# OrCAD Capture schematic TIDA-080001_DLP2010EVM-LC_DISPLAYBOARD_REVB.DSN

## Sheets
1 P05: DLPA2005: size D
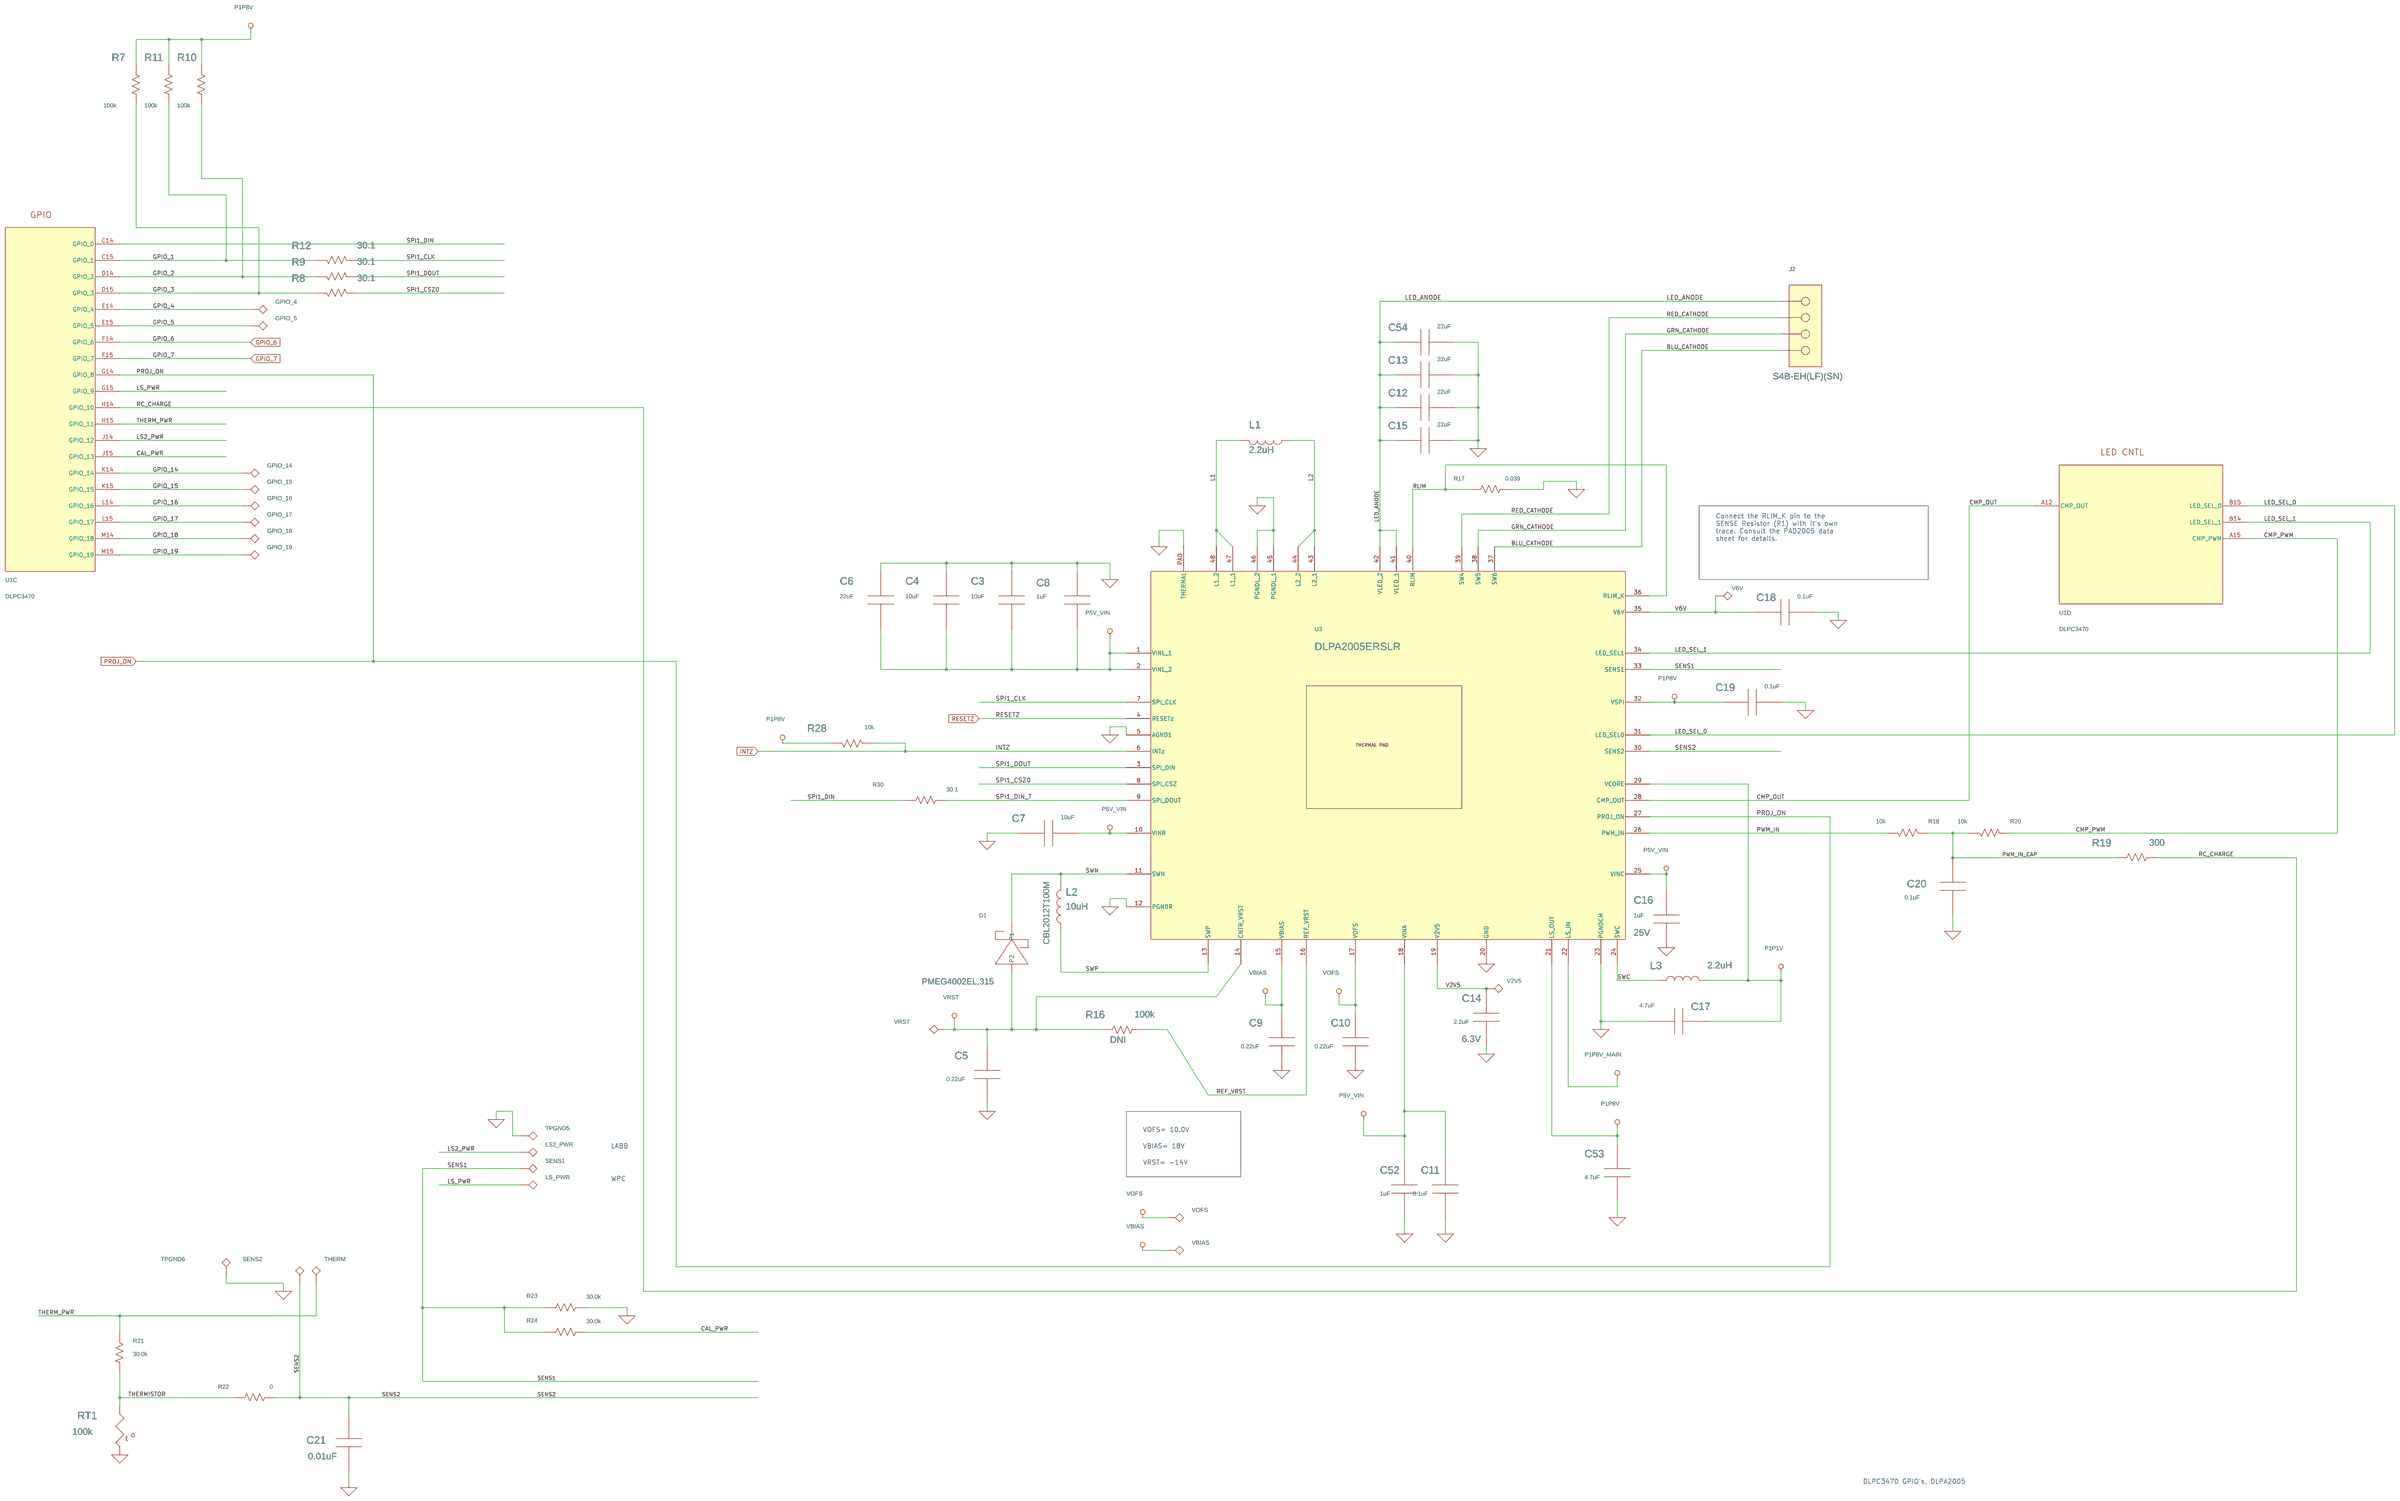
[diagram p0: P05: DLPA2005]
2 P07: Notice
3 P04: DMD Connection: size D
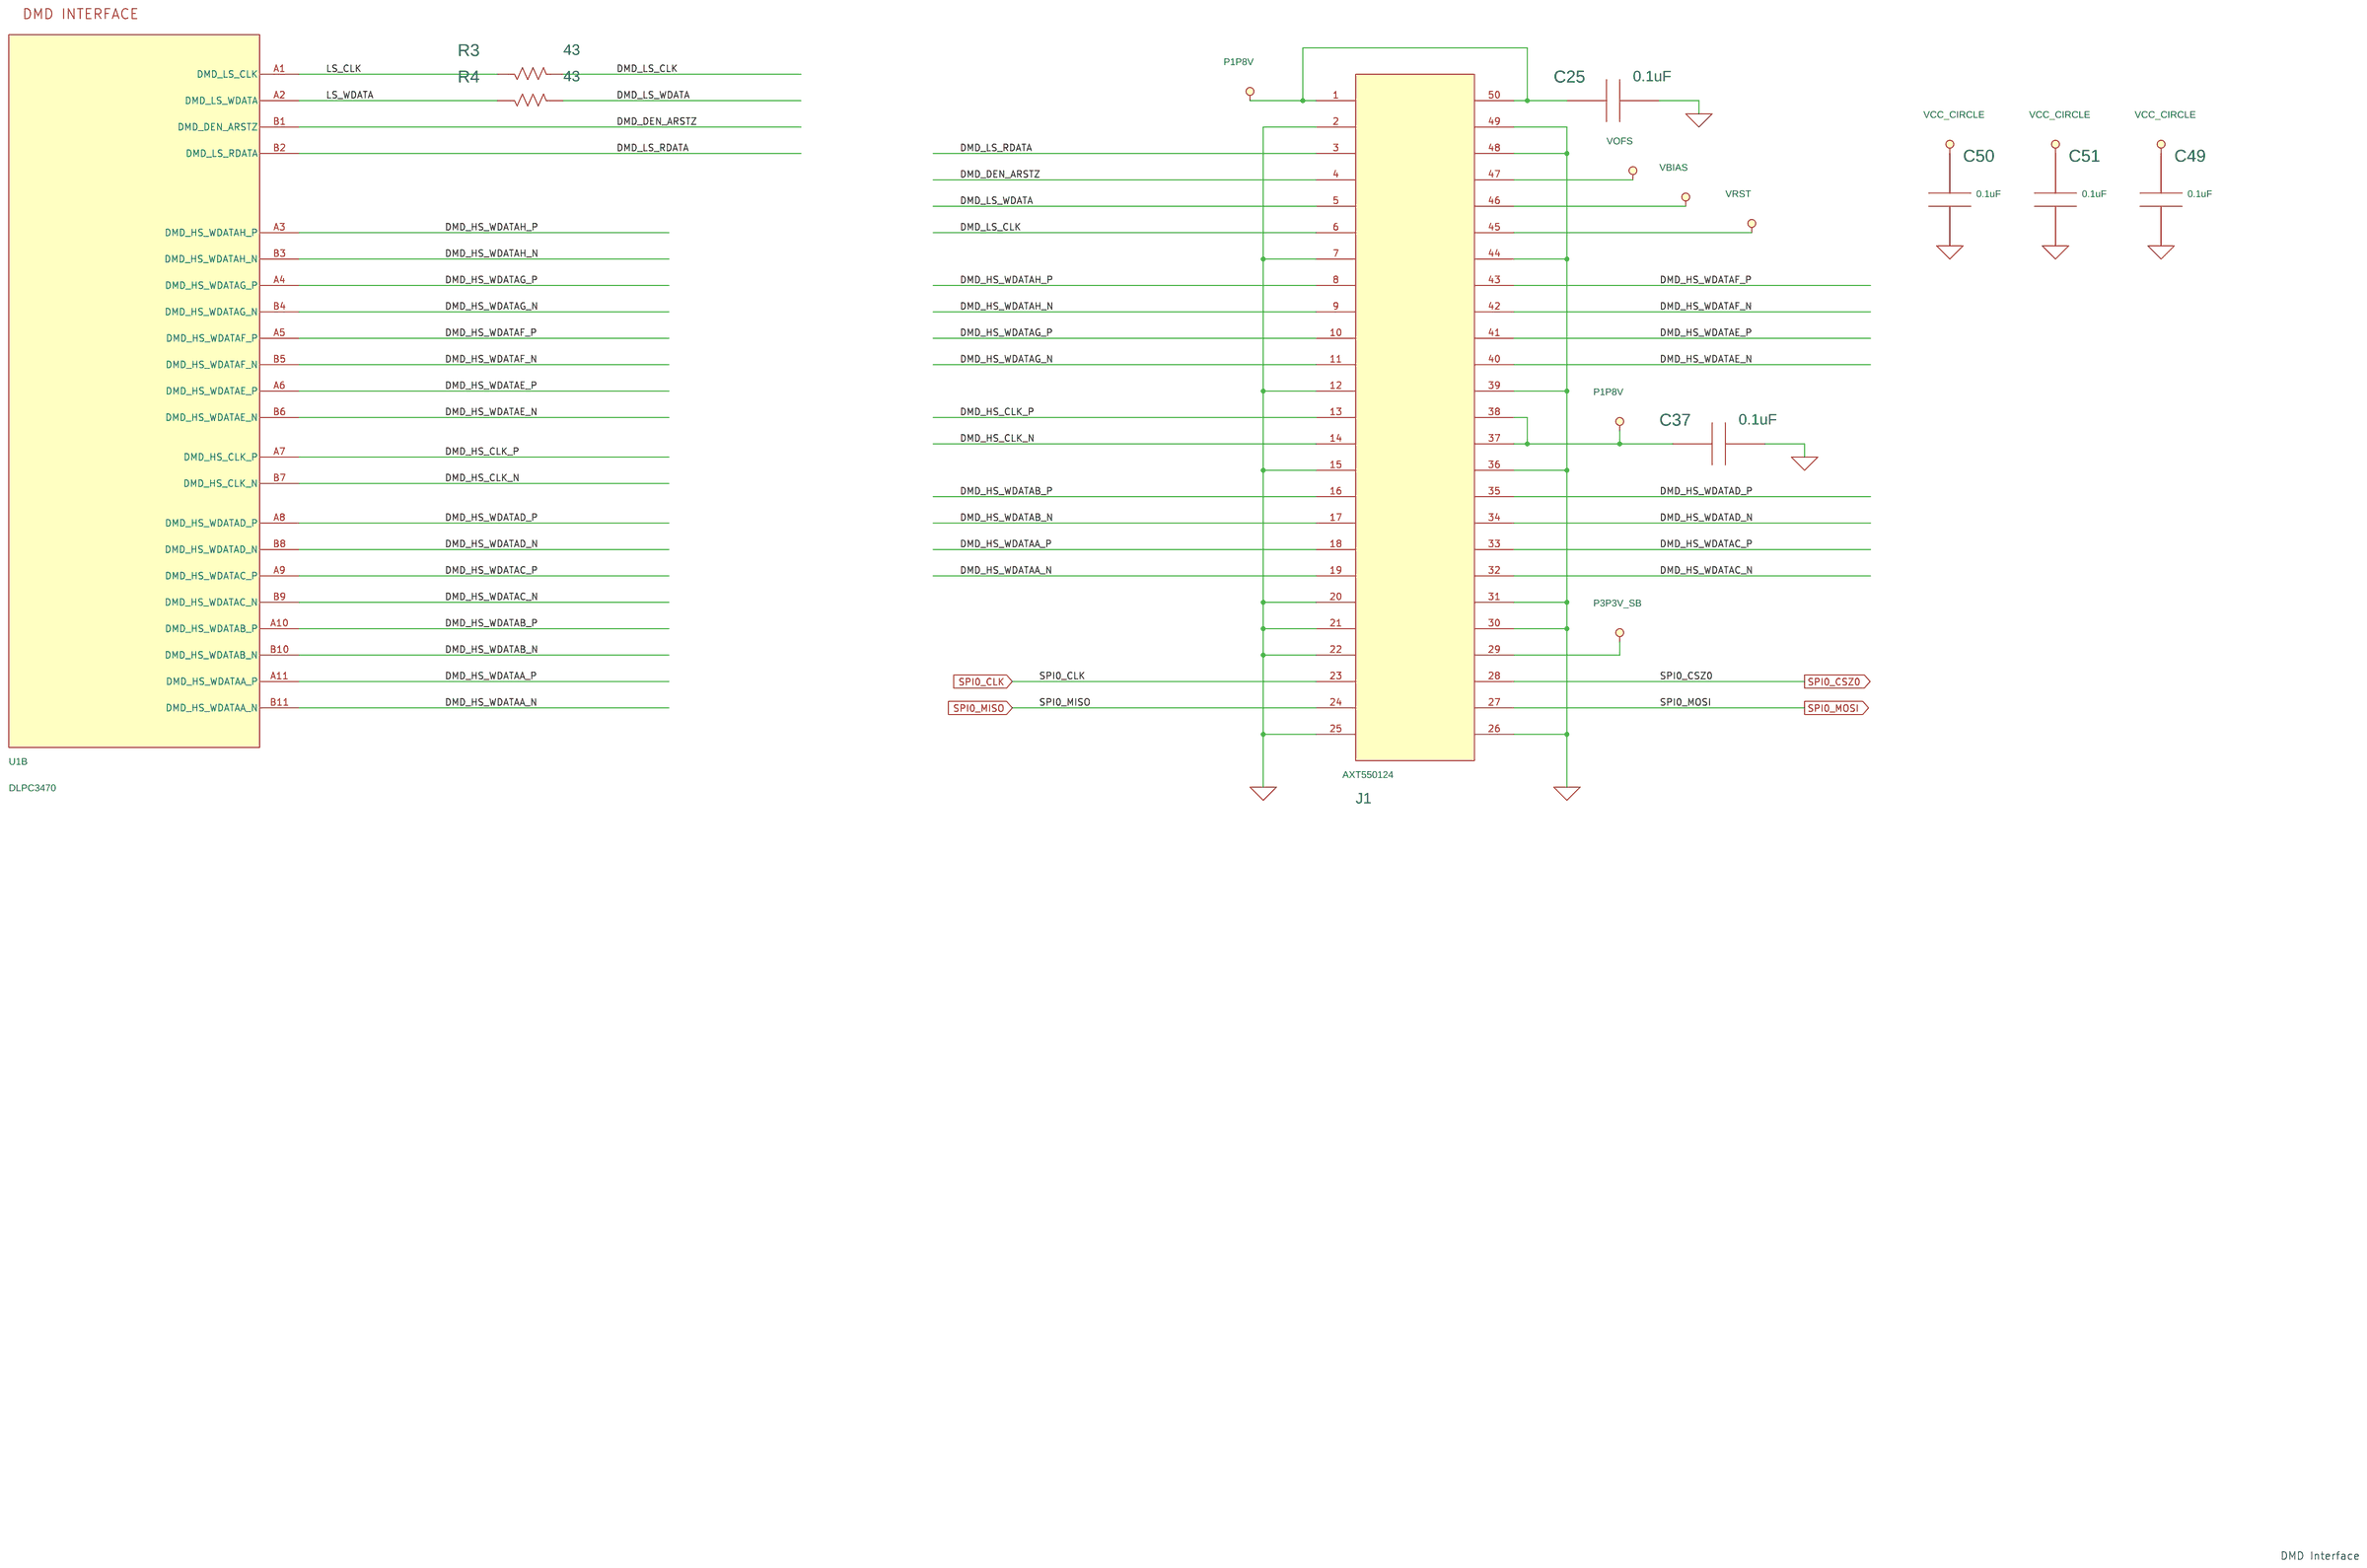
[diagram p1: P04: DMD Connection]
4 P01: DLP2010EVM-LC: title: TIDA-080001_DLP® 2010 Light Control Display Board; rev: B; company: Texas Instruments Inc.
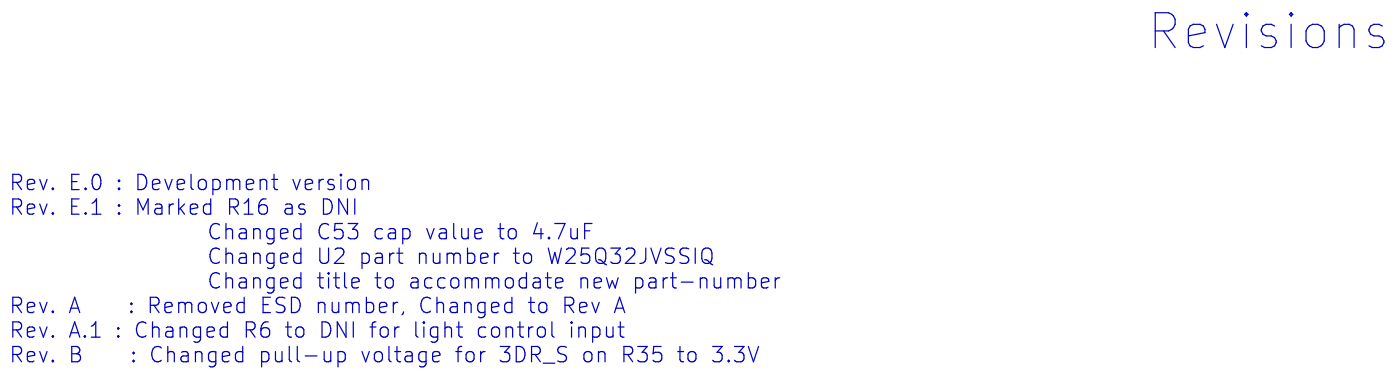
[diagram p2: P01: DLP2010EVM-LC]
5 P02: DLPC3470, Flash: size D
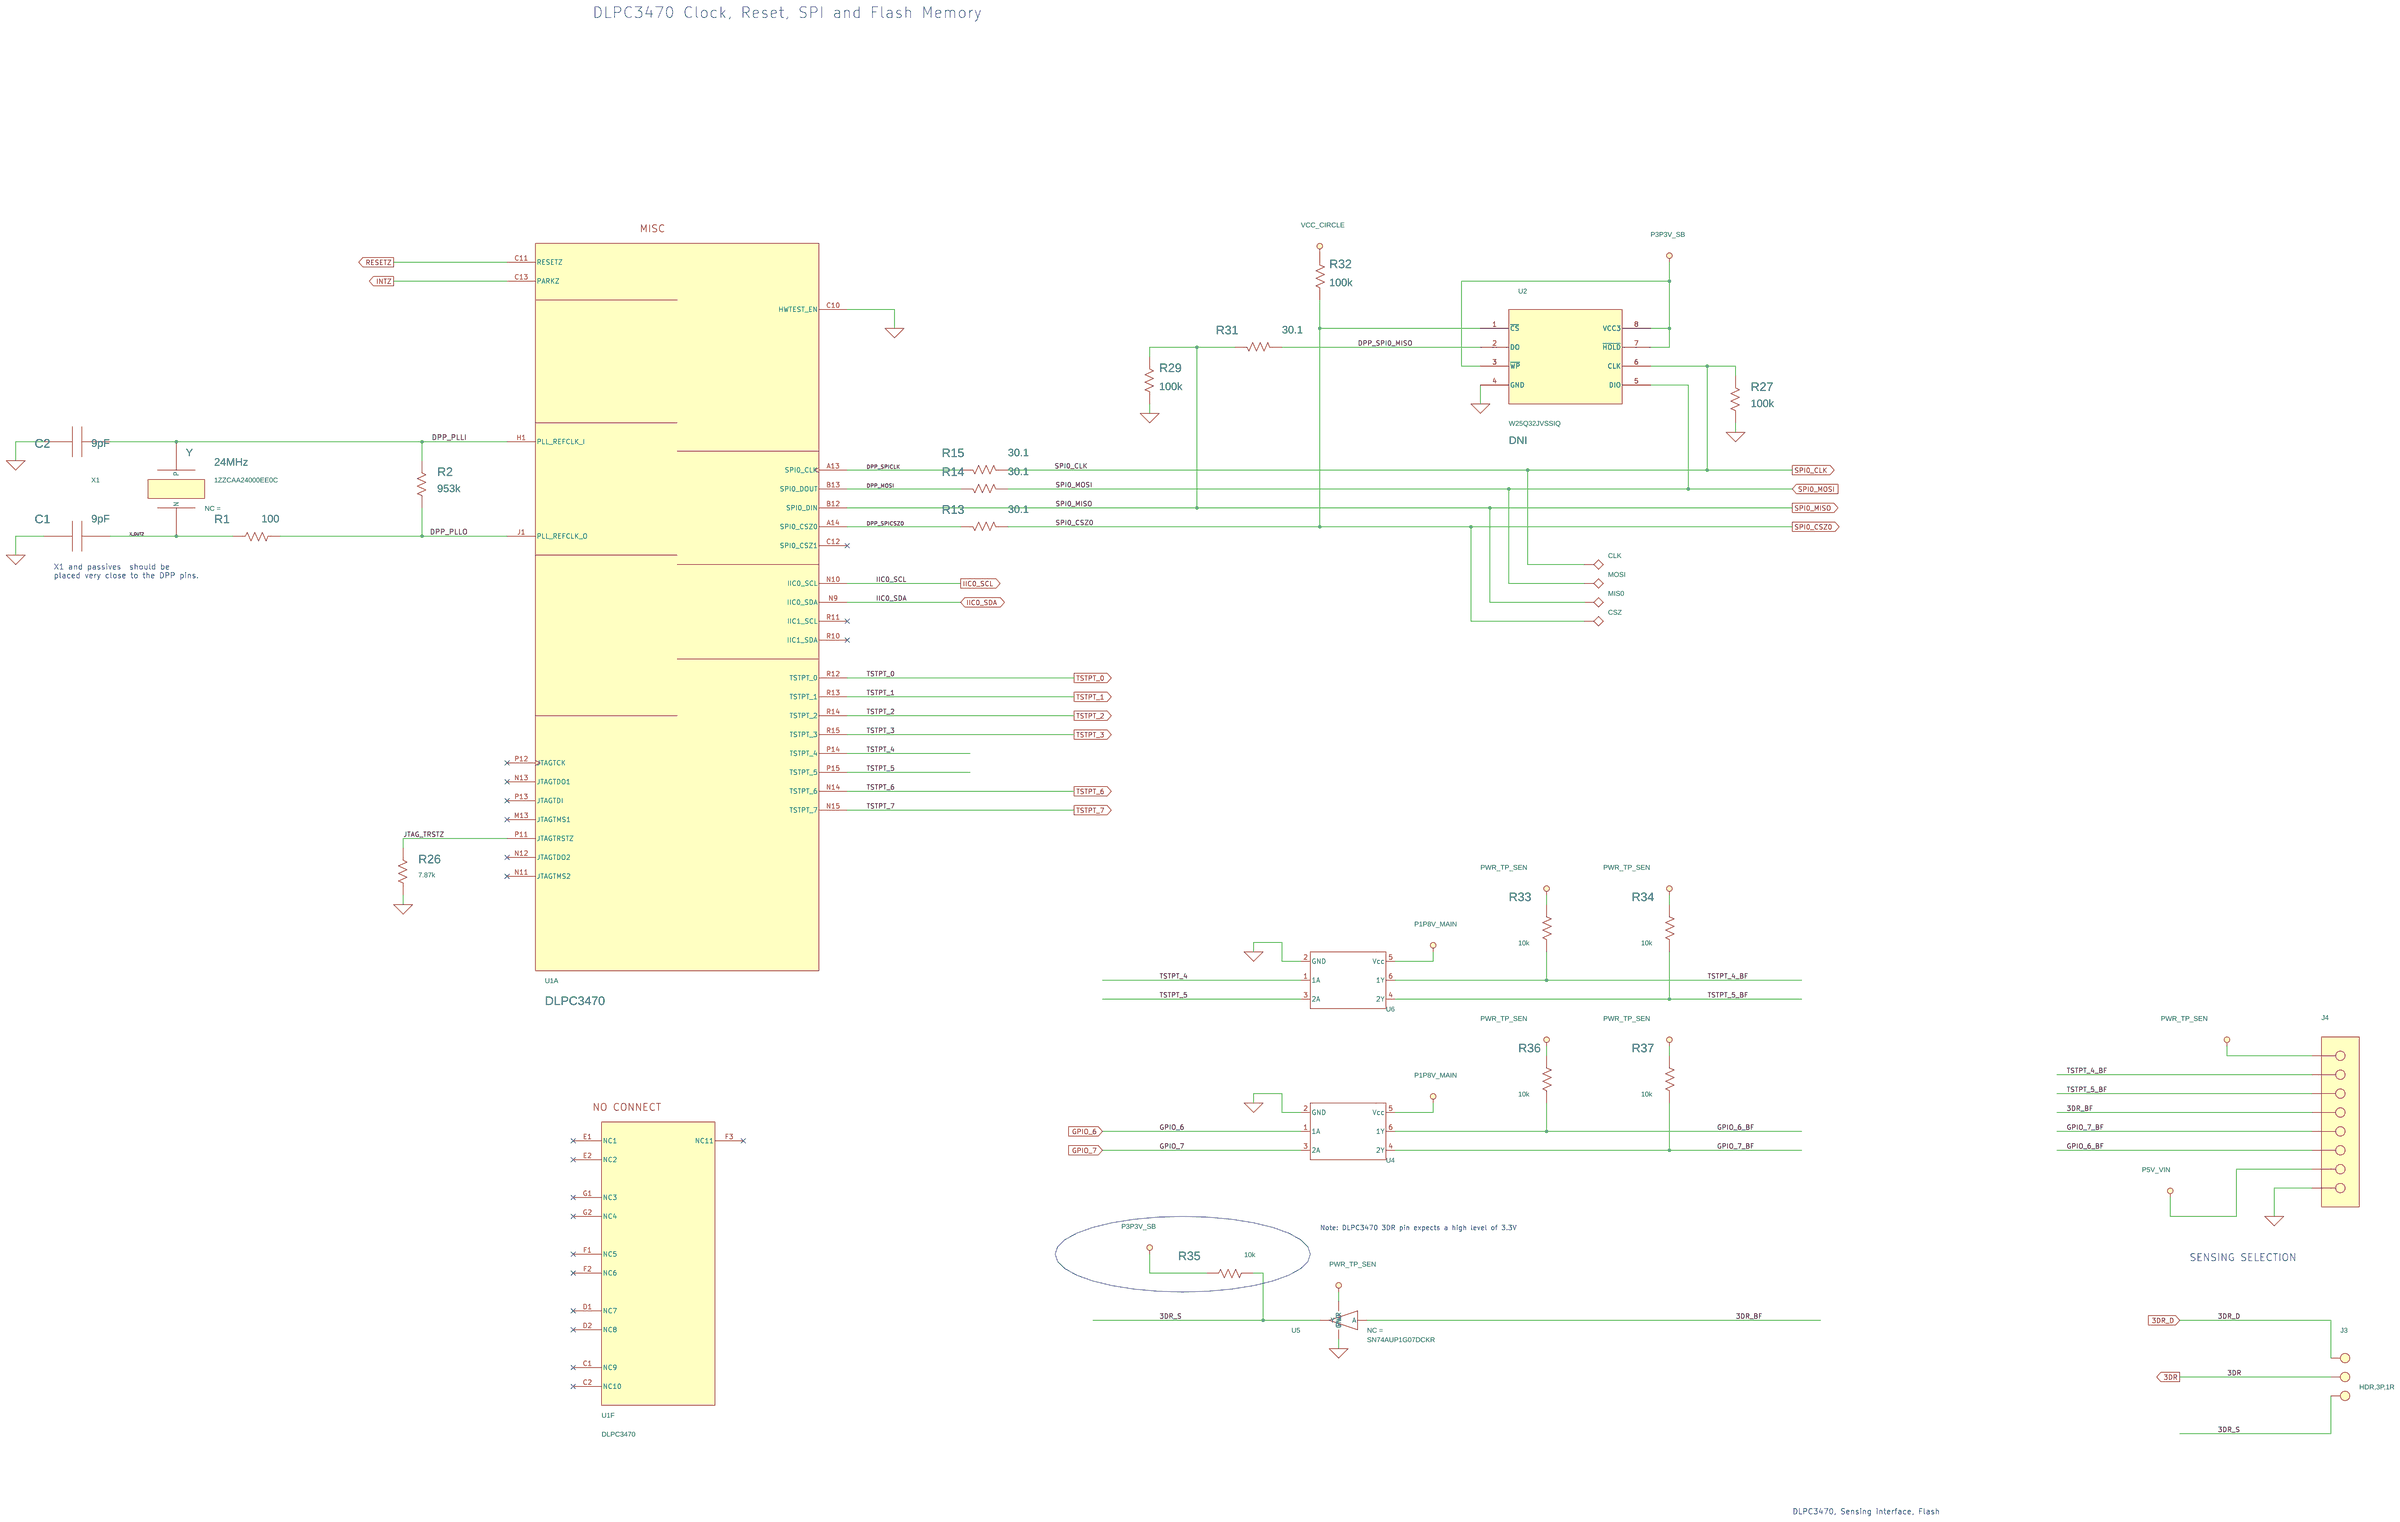
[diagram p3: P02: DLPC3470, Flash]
6 P06: DLPC3470 Power: size D
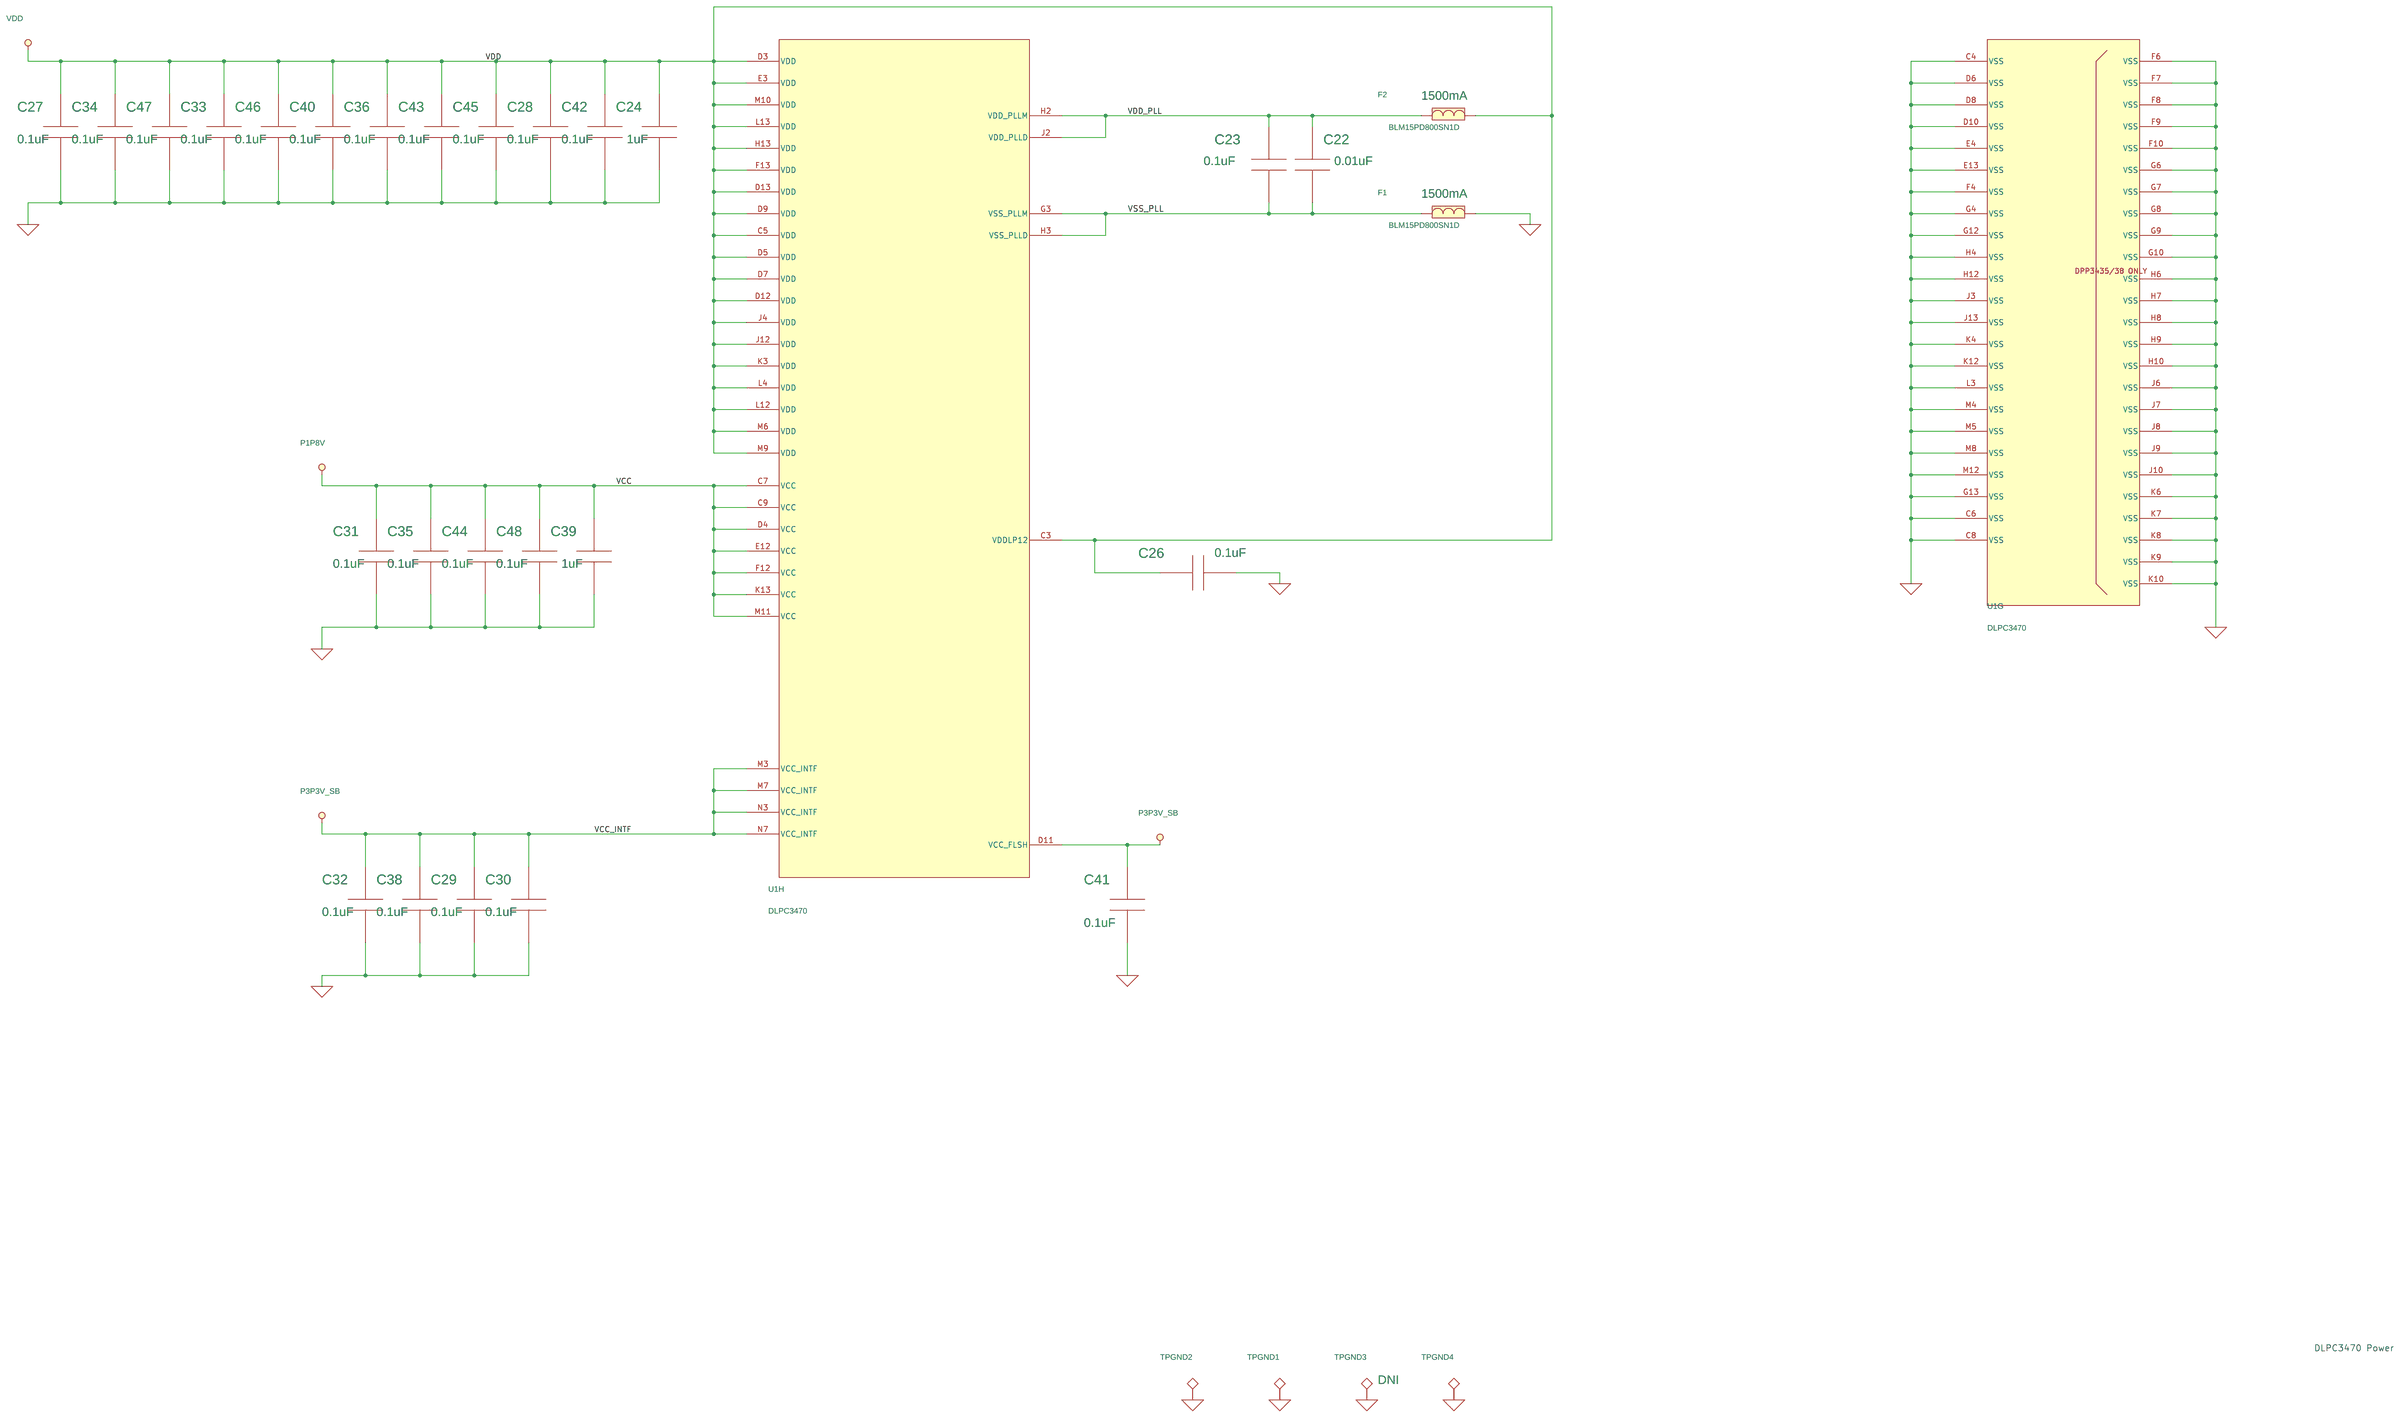
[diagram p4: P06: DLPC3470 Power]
7 P03: FrontEnd Connections: size D
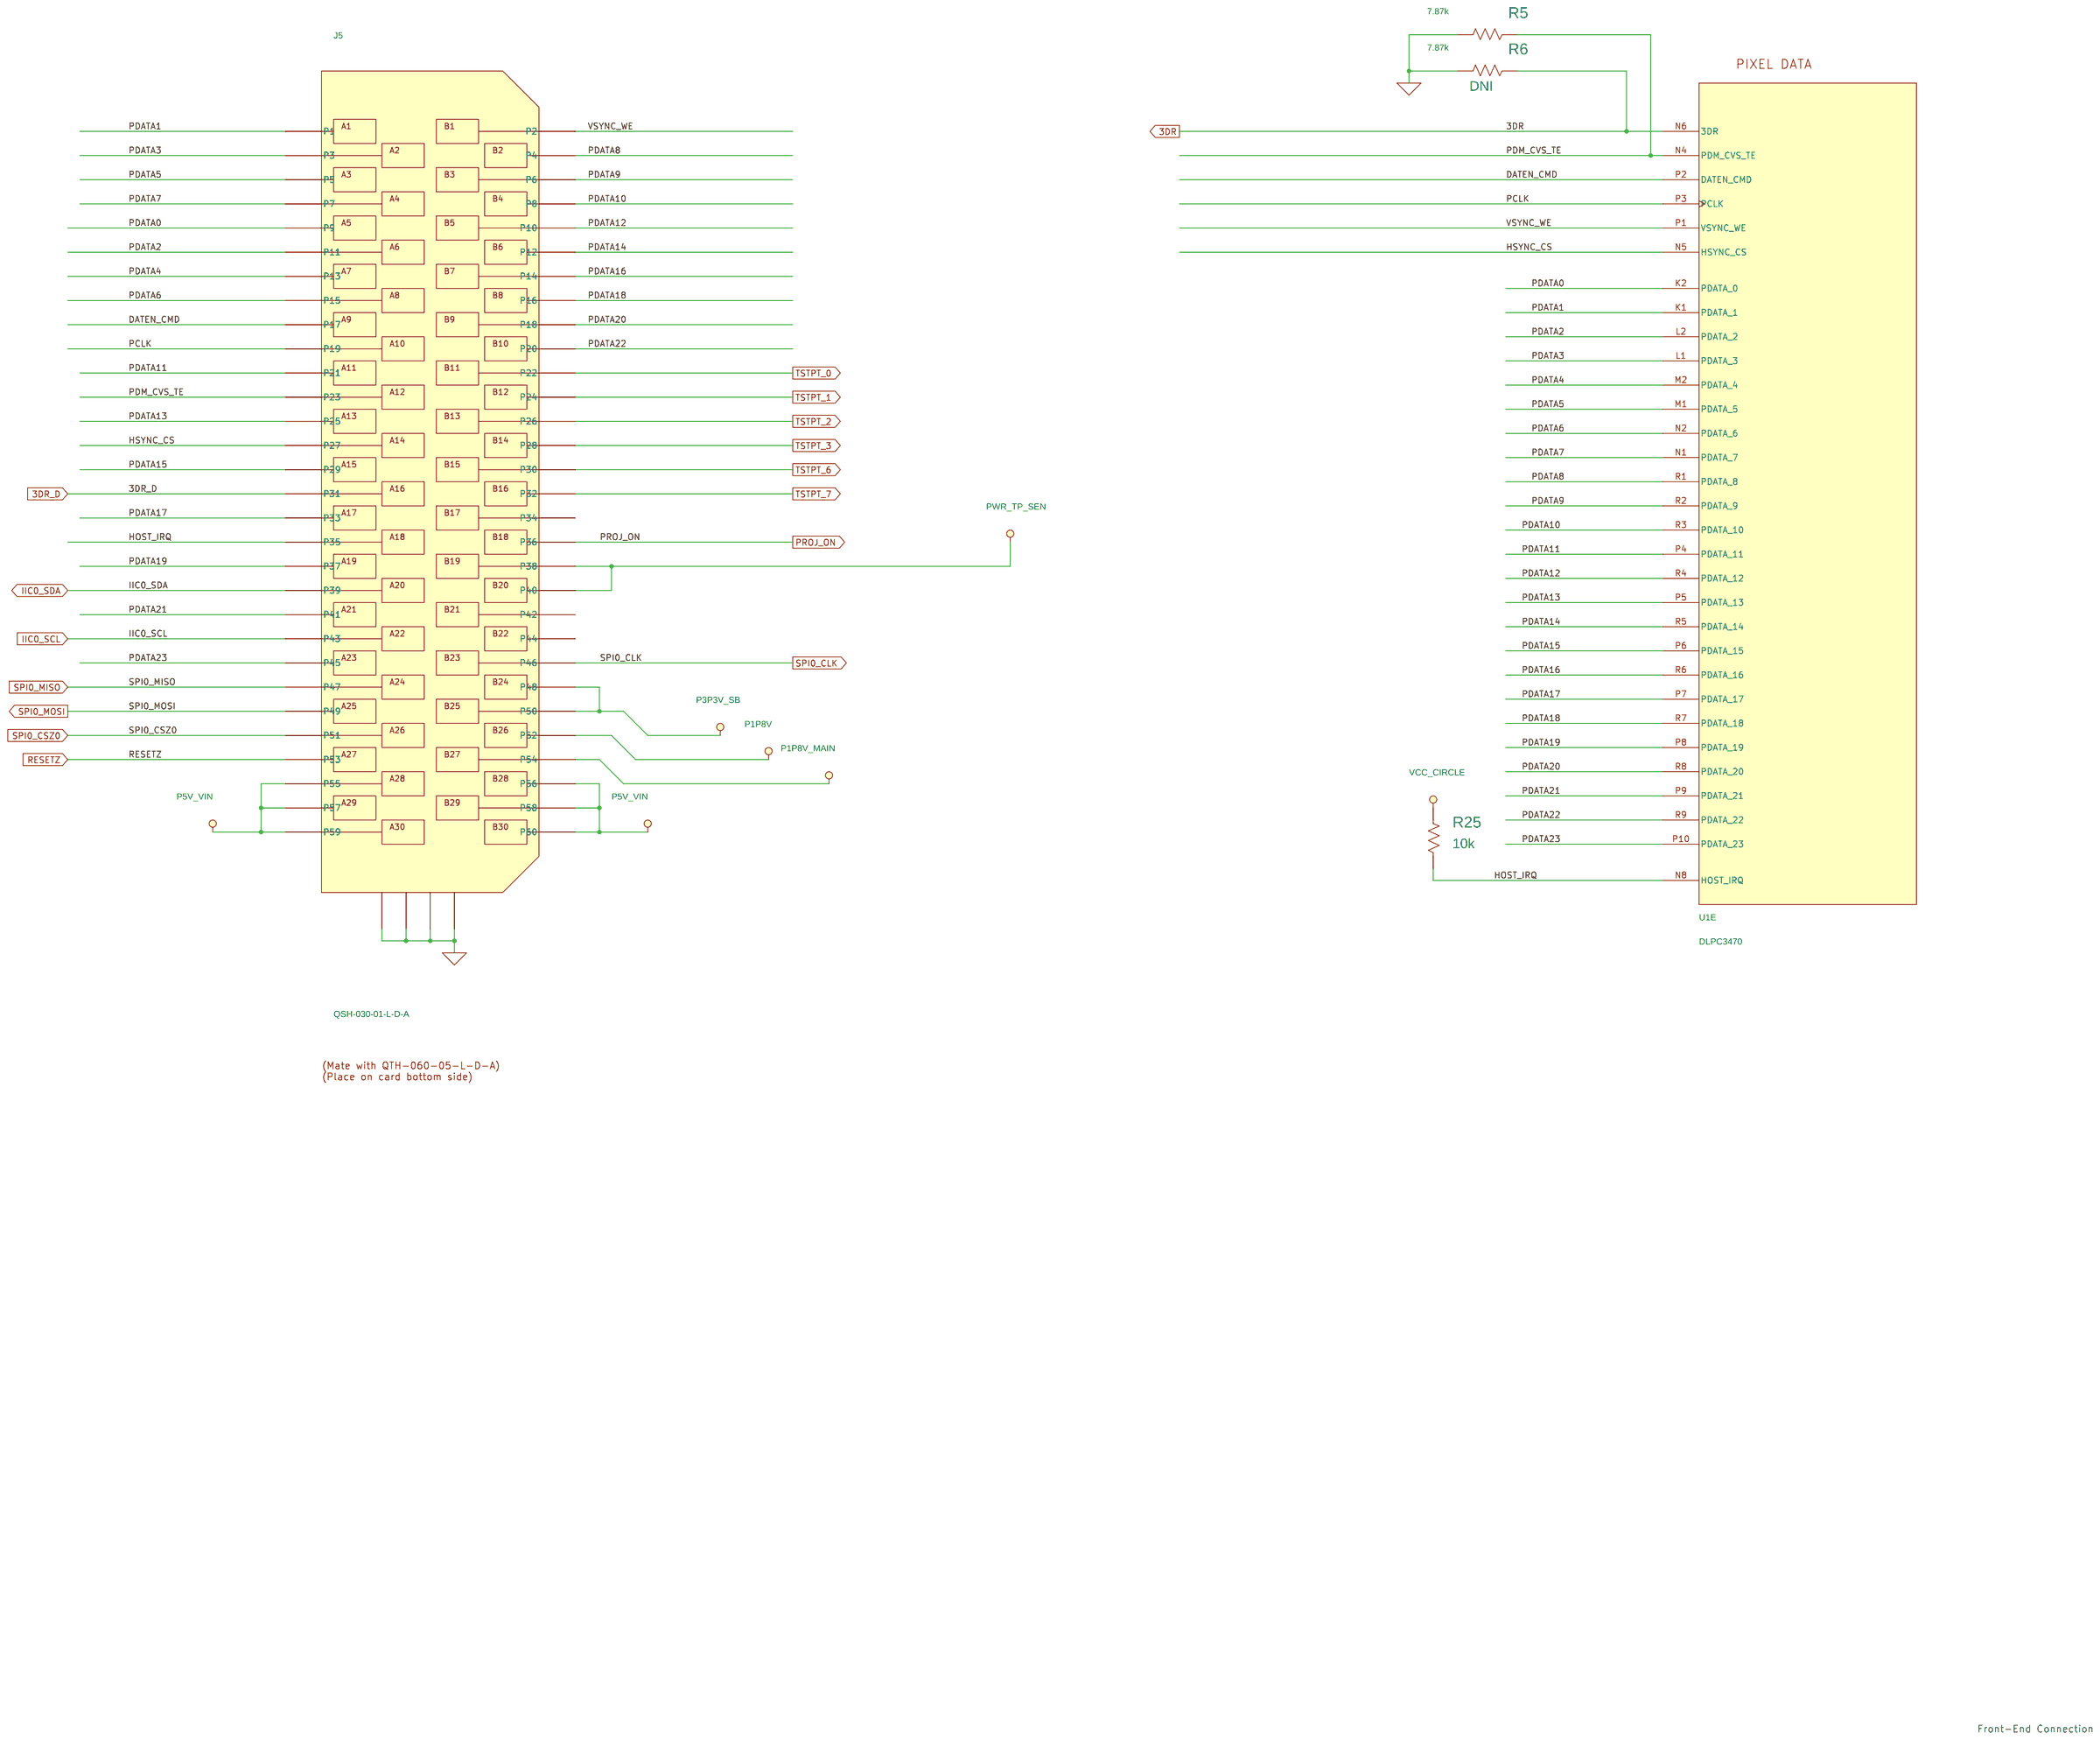
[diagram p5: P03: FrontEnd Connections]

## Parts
sheet P02: DLPC3470, Flash
C1  9pF  [0402]
C2  9pF  [0402]
CLK  TP,40mil Drill,60mil Pad  [HOLE_PLATED_40mil_DRILL_60mil_PAD]
CSZ  TP,40mil Drill,60mil Pad  [HOLE_PLATED_40mil_DRILL_60mil_PAD]
J3  HDR,3P,1R  [TSW-103-07-G-S]
J4  EM,HDR,8P,1R, 2.54  [HDR8x1]
MIS0  TP,40mil Drill,60mil Pad  [HOLE_PLATED_40mil_DRILL_60mil_PAD]
MOSI  TP,40mil Drill,60mil Pad  [HOLE_PLATED_40mil_DRILL_60mil_PAD]
R1  100  [0402]
R2  953k  [0402]
R13  30.1  [0402]
R14  30.1  [0402]
R15  30.1  [0402]
R26  7.87k  [0402]
R27  100k  [0402]
R29  100k  [0402]
R31  30.1  [0402]
R32  100k  [0402]
R33  10k  [0402]
R34  10k  [0402]
R35  10k  [0402]
R36  10k  [0402]
R37  10k  [0402]
U2  W25Q32JVSSIQ  [SOIC-8_208mil]
U4  SN74AUP2G07DCK  [U_6_DCK]
U5  SN74AUP1G07DCK  [U_5_DCK]
U6  SN74AUP2G07DCK  [U_6_DCK]
X1  24MHz  [NDK_EXS00A-CS05733]
sheet P03: FrontEnd Connections
J5  QSH-030-01-L-D-A  [Samtec_QSH-030-xx-x-D-A]
R5  7.87k  [0402]
R6  7.87k  [0402]
R25  10k  [0402]
sheet P04: DMD Connection
C25  0.1uF  [0402_AVXA]
C37  0.1uF  [0402_AVXA]
C49  0.1uF  [0402]
C50  0.1uF  [0402]
C51  0.1uF  [0402]
J1  AXT550124  [Panasonic_AXT550124_counter_clkwise_pinout]
R3  43  [0201]
R4  43  [0201]
sheet P05: DLPA2005
C3  10uF  [0603]
C4  10uF  [0603]
C5  0.22uF  [0402]
C6  22uF  [0603]
C7  10uF  [0603]
C8  1uF  [0402]
C9  0.22uF  [0402]
C10  0.22uF  [0402]
C11  0.1uF  [0402_AVXA]
C12  22uF  [0603]
C13  22uF  [0603]
C14  2.2uF  [0402]
C15  22uF  [0603]
C16  1uF  [0402]
C17  4.7uF  [0402]
C18  0.1uF  [0402_AVXA]
C19  0.1uF  [0402_AVXA]
C20  0.1uF  [0402_AVXA]
C21  0.01uF  [0402]
C52  1uF  [0402]
C53  4.7uF  [0402]
C54  22uF  [0603]
D1  PMEG4002EL  [SOD882]
GPIO_4  TP,20mil PAD  [tp20rd]
GPIO_5  TP,20mil PAD  [tp20rd]
GPIO_14  TP,20mil PAD  [tp20rd]
GPIO_15  TP,20mil PAD  [tp20rd]
GPIO_16  TP,20mil PAD  [tp20rd]
GPIO_17  TP,20mil PAD  [tp20rd]
GPIO_18  TP,20mil PAD  [tp20rd]
GPIO_19  TP,20mil PAD  [tp20rd]
J2  S4B-EH  [JST_S4B-EH]
L1  2.2uH  [CooperBussmann_DR74]
L2  10uH  [0805]
L3  2.2uH  [1008_2p5mmx2mm]
LS2_PWR  TP,40mil Drill,60mil Pad  [HOLE_PLATED_40mil_DRILL_60mil_PAD]
LS_PWR  TP,40mil Drill,60mil Pad  [HOLE_PLATED_40mil_DRILL_60mil_PAD]
R7  100k  [0402]
R8  30.1  [0402]
R9  30.1  [0402]
R10  100k  [0402]
R11  100k  [0402]
R12  30.1  [0402]
R16  100k  [0402]
R17  0.039  [0603]
R18  10k  [0402]
R19  300  [0402]
R20  10k  [0402]
R21  30.0k  [0402]
R22  0  [0402]
R23  30.0k  [0402]
R24  30.0k  [0402]
R28  10k  [0402]
R30  30.1  [0402]
RT1  100k  [0402]
SENS1  TP,40mil Drill,60mil Pad  [HOLE_PLATED_40mil_DRILL_60mil_PAD]
SENS2  TP,40mil Drill,60mil Pad  [HOLE_PLATED_40mil_DRILL_60mil_PAD]
THERM  TP,40mil Drill,60mil Pad  [HOLE_PLATED_40mil_DRILL_60mil_PAD]
TPGND5  TP,40mil Drill,60mil Pad  [HOLE_PLATED_40mil_DRILL_60mil_PAD]
TPGND6  TP,40mil Drill,60mil Pad  [HOLE_PLATED_40mil_DRILL_60mil_PAD]
U3  DLPA2005  [PAD2005_RSL_S-PQFP-N48_QFN48]
V2V5  TP,40mil Drill,60mil Pad  [HOLE_PLATED_40mil_DRILL_60mil_PAD]
V6V  TP,40mil Drill,60mil Pad  [HOLE_PLATED_40mil_DRILL_60mil_PAD]
VBIAS  TP,40mil Drill,60mil Pad  [HOLE_PLATED_40mil_DRILL_60mil_PAD]
VOFS  TP,40mil Drill,60mil Pad  [HOLE_PLATED_40mil_DRILL_60mil_PAD]
VRST  TP,40mil Drill,60mil Pad  [HOLE_PLATED_40mil_DRILL_60mil_PAD]
sheet P06: DLPC3470 Power
C22  0.01uF  [0402]
C23  0.1uF  [0402_AVXA]
C24  1uF  [0402]
C26  0.1uF  [0402_AVXA]
C27  0.1uF  [0402_AVXA]
C28  0.1uF  [0402_AVXA]
C29  0.1uF  [0402_AVXA]
C30  0.1uF  [0402_AVXA]
C31  0.1uF  [0402_AVXA]
C32  0.1uF  [0402_AVXA]
C33  0.1uF  [0402_AVXA]
C34  0.1uF  [0402_AVXA]
C35  0.1uF  [0402_AVXA]
C36  0.1uF  [0402_AVXA]
C38  0.1uF  [0402_AVXA]
C39  1uF  [0402]
C40  0.1uF  [0402_AVXA]
C41  0.1uF  [0402_AVXA]
C42  0.1uF  [0402_AVXA]
C43  0.1uF  [0402_AVXA]
C44  0.1uF  [0402_AVXA]
C45  0.1uF  [0402_AVXA]
C46  0.1uF  [0402_AVXA]
C47  0.1uF  [0402_AVXA]
C48  0.1uF  [0402_AVXA]
F1  BLM15PD800SN1D  [BLM15P]
F2  BLM15PD800SN1D  [BLM15P]
TPGND1  TP_BLK  [KEYSTONE_TP_MINIATURE]
TPGND2  TP_BLK  [KEYSTONE_TP_MINIATURE]
TPGND3  TP_BLK  [KEYSTONE_TP_MINIATURE]
TPGND4  TP_BLK  [KEYSTONE_TP_MINIATURE]
U1  DLPC3470  [DPP3438_13mmx13mm_VFBGA_201balls]  (sections A,B,C,D,E,F,G,H)

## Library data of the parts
C1 C2 = PAS,CAP,NP,large_2: DigiKey: 445-13284-1-ND; DigiReel: 445-13284-6-ND; Family: passive; Index PN: 1206; Install: Y; Lead Style: SMT; MFG: TDK; Material: npo; P/D_NUM: CGJ2B2C0G1H090D050BA; Part Number: CGJ2B2C0G1H090D050BA; Part Specific: CAP CER 9PF 50V NP0 0402; TOLERANCE: ±0.5pF; Type: capacitor; VENDOR: TDK; VPC: 50V
CLK CSZ LS2_PWR LS_PWR MIS0 MOSI SENS1 SENS2 THERM TPGND5 TPGND6 V2V5 V6V VBIAS VOFS VRST = BF,HOLE,PLATED,TESTPIN: DigiKey: ---; DigiReel: ---; Family: board feature; Index PN: 377; Install: DNI; Lead Style: TH; MFG: -- NOT A PART --; Type: hole,plated; Vendor: -- NOT A PART --
J3 = EM,JMP,3P,1R: DigiKey: SAM1029-03-ND; DigiReel: ---; Index PN: 20; Install: Y; Lead Style: TH; MFG: Samtec; Part Specific: PLUG; Pin Cnt: 3; Pin Spacing: 100mil; Row Cnt: 1; Type: header; Vendor: Samtec
J4 = EM,HDR,8P,1R,2X_1: DigiKey: 732-5321-ND; P/D_NUM: 61300811121; Part Number: 61300811121; Part Specific: CONN HEADER 8 POS 2.54; Type: Header Male; Vendor: Wurth Electronics Inc.
R1 = PAS,R,large: DigiKey: MCS0402-100-CFCT-ND; DigiReel: MCS0402-100-CFDKR-ND; Family: passive; Install: Y; Lead Style: SMT; MFG: Vishay Beyschlag; Material: chip; P/D_NUM: MCS04020C1000FE000; Part Number: MCS04020C1000FE000; Part Specific: RES 100 OHM 1/10W 1% 0402 SMD; Power: 1/10W; TOLERANCE: 1%; Type: resistor; VENDOR: Vishay Beyschlag; VPC: 1/10W
R2 = PAS,R,large: DigiKey: P953KLCT-ND; DigiReel: P953KLDKR-ND; Family: passive; Index PN: 969; Install: Y; Lead Style: SMT; MFG: Panasonic; Material: chip; P/D_NUM: ERJ-2RKF9533X; Part Number: ERJ-2RKF9533X; Part Specific: RES 953K OHM 1/10W 1% 0402 SMD; TOLERANCE: 1%; Type: resistor; VENDOR: Panasonic; VPC: 1/16W
R8 R9 R12-R15 R31 = PAS,R,large: DigiKey: YAG3111CT-ND; DigiReel: YAG3111DKR-ND; Family: passive; Lead Style: SMT; MFG: Yageo; Material: chip; P/D_NUM: RC0402FR-0730R1L; Part Number: RC0402FR-0730R1L; Part Specific: RES 30.1 OHM 1/16W 1% 0402 SMD; Power: 1/16W; TOLERANCE: 1%; Type: resistor; VENDOR: Yageo; VPC: 1/16W
R5 R26 = PAS,R,large: DigiKey: P7.87KLCT-ND; DigiReel: P7.87KLDKR-ND; Family: passive; Index PN: 1175; Lead Style: SMT; MFG: Panasonic; Material: chip; P/D_NUM: ERJ-2RKF7871X; Part Number: ERJ-2RKF7871X; Part Specific: RES 7.87K OHM 1/10W 1% 0402 SMD; Type: resistor; VENDOR: Panasonic; VPC: 1/10W
R7 R10 R11 R27 R29 R32 = PAS,R,large: DigiKey: 311-100KLRCT-ND; DigiReel: 311-100KLRDKR-ND; Family: passive; Lead Style: SMT; MFG: Yageo; Material: chip; P/D_NUM: RC0402FR-07100KL; Part Number: RC0402FR-07100KL; Part Specific: RES 100K OHM 1/16W 1% 0402 SMD; Power: 1/16W; TOLERANCE: 1%; Type: resistor; VENDOR: Yageo; VPC: 1/16W
R28 R33-R37 = PAS,R,large: DigiKey: P10.0KLCT-ND; DigiReel: P10.0KLDKR-ND; Family: passive; Index PN: 680; Lead Style: SMT; MFG: Panasonic; Material: chip; P/D_NUM: ERJ-2RKF1002X; Part Number: ERJ-2RKF1002X; Part Specific: RES SMD 10K OHM 1% 1/10W 0402; Power: 1/16W; TOLERANCE: 1%; Type: resistor; VENDOR: Panasonic; VPC: 1/16W
U2 = MEM,FLASH,SERIAL,W25XxxALxNIG: DigiKey: W25Q32JVSSIQ-ND; Family: memory; Install: DNI; Lead Style: SMT; MFG: Winbond; Part Specific: IC FLASH SPI 32MBIT 8SOIC; Type: flash, spi; VPC: 2.7-3.6V
U4 U6 = TMP_134645: DigiKey: 296-27357-1-ND; DigiReel: 296-27357-6-ND; Family: logic; MFG: Texas Instruments; Part Number: SN74AUP2G07DCKR; Part Specific: IC BUFF/DRIVER DUAL LP SC70-6; Type: buffer
U5 = LOG,BUF,OPENDRN,SN74AUP1G07DCK: DigiKey: 296-18256-1-ND; DigiReel: 296-18256-6-ND; Family: logic; Index PN: 1027; Lead Style: SMT; MFG: Texas Instruments; P/D_NUM: SN74AUP1G07DCKR; Part Number: SN74AUP1G07DCKR; Part Specific: IC BUFF/DVR LOW PWR N-INV SC705, open drain; Type: buffer
X1 = XTAL_NX3225GA: DigiKey: ---; DigiReel: ---; Family: passive; Index PN: 1155; Install: Y; Lead Style: SMT; MFG: KDS; P/D_NUM: 1ZZCAA24000EE0C; Part Number: 1ZZCAA24000EE0C; Part Specific: Type NX2016SA, 24MHz; Type: crystal; VENDOR: NDK
J5 = EM,CONN,60P,QSx: DigiKey: SAM8180-ND; Family: electro/mechanical; Index PN: 1061; Lead Style: SMT; MFG: Samtec; Part Specific: CONN RCPT HI-SPD .5MM 60POS DL (stacking ht 5mm); Pin Cnt: 60; Pin Spacing: 0.5mm; Row Cnt: 2; Type: connector; Vendor: Samtec
R6 = PAS,R,large: DigiKey: P7.87KLCT-ND; DigiReel: P7.87KLDKR-ND; Family: passive; Index PN: 1175; Install: DNI; Lead Style: SMT; MFG: Panasonic; Material: chip; P/D_NUM: ERJ-2RKF7871X; Part Number: ERJ-2RKF7871X; Part Specific: RES 7.87K OHM 1/10W 1% 0402 SMD; Type: resistor; VENDOR: Panasonic; VPC: 1/10W
R25 = PAS,R,large: DigiKey: P10.0KLCT-ND; DigiReel: P10.0KLDKR-ND; Family: passive; Index PN: 680; Install: Y; Lead Style: SMT; MFG: Panasonic; Material: chip; P/D_NUM: ERJ-2RKF1002X; Part Number: ERJ-2RKF1002X; Part Specific: RES SMD 10K OHM 1% 1/10W 0402; Power: 1/16W; TOLERANCE: 1%; Type: resistor; VPC: 1/16W; Vendor: Panasonic
C23 C25-C38 C40-C48 = PAS,CAP,NP,large_2: DigiKey: 445-4952-1-ND; DigiReel: 445-4952-6-ND; Family: passive; Index PN: 681; Lead Style: SMT; MFG: TDK; Material: x7r; P/D_NUM: C1005X7R1C104K050BC; Part Number: C1005X7R1C104K050BC; Part Specific: CAP CER .1UF 16V X7R 0402; TOLERANCE: 10%; Type: capacitor; VENDOR: TDK; VPC: 16V
C49-C51 = PAS,CAP,NP,large_2: DigiKey: 445-6899-1-ND; DigiReel: 445-6899-6-ND; Family: passive; Lead Style: SMT; MFG: TDK; Material: X7R; P/D_NUM: CGA2B3X7R1H104K050BB; Part Number: CGA2B3X7R1H104K050BB; Part Specific: 0.10µF 50V Ceramic Capacitor X7R 0402; TOLERANCE: 10%; Type: capacitor; VENDOR: TDK; VPC: 50V
J1 = EM,CONN,50P,2R,CNTR_CW_PINOUT: DigiKey: 255-2408-1-ND; DigiReel: 255-2408-6-ND; Family: electro/mechanical; Index PN: 1235; Lead Style: SMT; MFG: Panasonic; Part Specific: CONN SOCKET F4S .4MM 50POS SMD; Pin Cnt: 50; Pin Spacing: 0.4mm; Row Cnt: 2; Type: connector; Vendor: Panasonic
R3 R4 = PAS,R,large: DigiKey: P43AGCT-ND; DigiReel: P43AGDKR-ND; Family: passive; Index PN: 1167; Lead Style: SMT; MFG: Panasonic; P/D_NUM: ERJ-1GEJ430C; Part Number: ERJ-1GEJ430C; Part Specific: RES 43 OHM 1/20W 5% 0201 SMD; TOLERANCE: 5%; Type: resistor; VENDOR: Panasonic
C3 C4 C7 = PAS,CAP,NP,large_2: DigiKey: 445-6853-1-ND; DigiReel: 445-6853-6-ND; Family: passive; Index PN: 1207; Lead Style: SMT; MFG: TDK; P/D_NUM: C1608X5R1A106M080AC; Part Number: C1608X5R1A106M080AC; Part Specific: CAP CER 10UF 10V 20% X5R 0603; TOLERANCE: 20%; Type: capacitor; VENDOR: TDK; VPC: 10V; Voltage: 6.3V
C5 C9 C10 = PAS,CAP,NP,large_2: DigiKey: 445-5944-1-ND; DigiReel: 445-5944-6-ND; Family: passive; Index PN: 1173; Lead Style: SMT; MFG: TDK; Material: x5r; P/D_NUM: C1005X5R1E224K050BC; Part Number: C1005X5R1E224K050BC; Part Specific: CAP CER 0.22UF 25V 10% X5R 0402; TOLERANCE: 10%; Type: capacitor; VENDOR: TDK; VPC: 25V; Voltage: 25V
C6 = PAS,CAP,NP,large_2: DigiKey: 1276-1274-1-ND; DigiReel: 1276-1274-6-ND; Family: passive; Lead Style: SMT; MFG: Samsung; Material: x5r; P/D_NUM: CL10A226MP8NUNE; Part Number: C1608X5R1A226M080AC; Part Specific: CAP CER 22UF 10V 20% X5R 0603; TOLERANCE: 20%; Type: capacitor; VENDOR: Samsung; VPC: 10V; Voltage: 10V
C8 C16 = PAS,CAP,NP,large_2: DigiKey: 587-3245-1-ND; DigiReel: 587-3245-6-ND; Family: passive; Lead Style: SMT; MFG: Taiyo Yuden; Material: x5r; P/D_NUM: TMK105BJ105MV-F; Part Number: TMK105BJ105MV-F; Part Specific: CAP CER 1.0UF 25V X5R 0402; TOLERANCE: 20%; Type: capacitor; VENDOR: Taiyo Yuden; VPC: 25V; Voltage: 25V
C11 C19 = PAS,CAP,NP,large_2: DigiKey: 445-4952-1-ND; DigiReel: 445-4952-6-ND; Family: passive; Index PN: 681; Lead Style: SMT; MFG: TDK; Material: x7r; P/D_NUM: C1005X7R1C104K050BC; Part Number: C1005X7R1C104K050BC; Part Specific: CAP CER .1UF 16V X7R 0402; TOLERANCE: 10%; Type: capacitor; VENDOR: TDK; VPC: 16V; Voltage: 16V
C12 C13 C15 C54 = PAS,CAP,NP,large_2: DigiKey: 445-8028-1-ND; DigiReel: 445-8028-6-ND; Family: passive; Index PN: 1171; Lead Style: SMT; MFG: TDK; Material: x5r; P/D_NUM: C1608X5R0J226M; Part Number: C1608X5R0J226M; Part Specific: CAP CER 22UF 6.3V 20% X5R 0603; TOLERANCE: 20%; Type: capacitor; VENDOR: TDK; VPC: 6.3V; Voltage: 6.3V
C14 = PAS,CAP,NP,large_2: DigiKey: 445-4999-1-ND; DigiReel: 445-4999-6-ND; Family: passive; Index PN: 915; Lead Style: SMT; MFG: TDK; Material: x5r; P/D_NUM: C1005X5R0J225M; Part Number: C1005X5R0J225M; Part Specific: CAP CER 2.2UF 6.3V X5R 0402; TOLERANCE: 10%; Type: capacitor; VENDOR: TDK; VPC: 6.3V; Voltage: 25V
C17 = PAS,CAP,NP,large_2: DigiKey: 445-7395-1-ND; DigiReel: 445-7395-6-ND; Family: passive; Lead Style: SMT; MFG: TDK; Material: x5r; P/D_NUM: C1005X5R0J475M050BC; Part Number: C1005X5R0J475M050BC; Part Specific: CAP CER 4.7UF 6.3V 20% X5R 0402; Type: capacitor; VENDOR: TDK; VPC: 6.3V; Voltage: 6.3V
C18 C20 = PAS,CAP,NP,large_2: DigiKey: 445-4952-1-ND; DigiReel: 445-4952-6-ND; Family: passive; Index PN: 681; Lead Style: SMT; MFG: TDK; Material: x7r; P/D_NUM: C1005X7R1C104K050BC; Part Number: C1005X7R1C104K050BC; Part Specific: CAP CER .1UF 16V X7R 0402; TOLERANCE: 10%; Type: capacitor; VENDOR: TDK; VPC: 16V; Voltage: 25V
C21 = PAS,CAP,NP,large_2: DigiKey: 445-1262-1-ND; DigiReel: 445-1262-6-ND; Family: passive; Index PN: 908; Lead Style: SMT; MFG: TDK; Material: x7r; P/D_NUM: C1005X7R1C103K; Part Number: C1005X7R1C103K; Part Specific: CAP CER 10000PF 16V X7R 10% 0402; TOLERANCE: 10%; Type: capacitor; VENDOR: TDK; VPC: 16V; Voltage: 16V
C52 = PAS,CAP,NP,large_2: DigiKey: 587-3245-1-ND; DigiReel: 587-3245-6-ND; Family: passive; Lead Style: SMT; MFG: TDK; Material: x5r; P/D_NUM: TMK105BJ105MV-F; Part Number: TMK105BJ105MV-F; Part Specific: CAP CER 1.0UF 25V X5R 0402; TOLERANCE: 20%; Type: capacitor; VENDOR: Taiyo Yuden; VPC: 25V; Voltage: 25V
C53 = PAS,CAP,NP,large_2: DigiKey: 445-7395-1-ND; DigiReel: 445-7395-6-ND; Family: passive; Lead Style: SMT; MFG: TDK; Material: x5r; P/D_NUM: C1005X5R0J475M050BC; Part Number: C1005X5R0J475M050BC; Part Specific: CAP CER 4.7UF 6.3V X5R 0402; TOLERANCE: 20%; Type: capacitor; VENDOR: TDK; VPC: 6.3V; Voltage: 6.3V
D1 = PAS,DIODE,SCHOTTKY,large: DigiKey: 568-4131-1-ND; DigiReel: 568-4131-6-ND; Family: passive; Index PN: 907; Lead Style: SMT; MFG: NXP Semiconductors; P/D_NUM: PMEG4002EL,315; Part Number: PMEG4002EL,315; Part Specific: SCHOTTKY RECT 40V 0.2A SOD882; Type: diode,schottky; VENDOR: NXP Semiconductors; VPC: 40V; Voltage: 40V
GPIO_4 GPIO_5 GPIO_14-GPIO_19 = BF,HOLE,PLATED,TESTPIN: Family: board feature; Index PN: 1145; Install: DNI; Lead Style: SMT; MFG: -- NOT A PART --; Type: pad pattern; Vendor: -- NOT A PART --
J2 = EM,HDR,4P,1R,2x: DigiKey: 455-1627-ND; Family: electro/mechanical; Index PN: 1245; Lead Style: TH; MFG: JST; P/D_NUM: S4B-EH(LF)(SN); Part Number: S4B-EH(LF)(SN); Part Specific: CONN HEADER EH SIDE 4POS 2.5MM; Pin Cnt: 4; Pin Spacing: 2.5MM; Row Cnt: 1; Type: header; Vendor: JST
L1 = PAS,INDUCTOR,_large: DigiKey: 513-1140-1-ND; DigiReel: 513-1140-6-ND; Family: passive; Index PN: 1249; Lead Style: SMT; MFG: Cooper Bussmann; P/D_NUM: DR74-2R2-R; Part Number: DR74-2R2-R; Part Specific: INDUCTOR SHIELD PWR 2.2UH SMD Irms-4.76A Isat-7.06A; Type: inductor; VENDOR: Cooper Bussmann; VPC: 4.76A
L2 = PAS,INDUCTOR,_large: DigiKey: 587-1632-1-ND; DigiReel: 587-1632-6-ND; Family: passive; Index PN: 901; Lead Style: SMT; MFG: Taiyo Yuden; P/D_NUM: CBL2012T100M; Part Number: CBL2012T100M; Part Specific: INDUCTOR 10UH 20% 0805 SMD; Type: inductor; VENDOR: Taiyo Yuden
L3 = PAS,INDUCTOR,_large: DigiKey: 490-5114-1-ND; DigiReel: 490-5114-6-ND; Family: passive; Index PN: 1149; Lead Style: SMT; MFG: Murata; P/D_NUM: LQM2HPN2R2MG0L; Part Number: LQM2HPN2R2MG0L; Part Specific: INDUCTOR 2.2UH 20% 1300MA 1008; Type: inductor; VENDOR: Murata
R16 = PAS,R,large: DigiKey: 311-100KLRCT-ND; DigiReel: 311-100KLRDKR-ND; Family: passive; Install: DNI; Lead Style: SMT; MFG: Yageo; Material: chip; P/D_NUM: RC0402FR-07100KL; Part Number: RC0402FR-07100KL; Part Specific: RES 100K OHM 1/16W 1% 0402 SMD; Power: 1/16W; TOLERANCE: 1%; Type: resistor; VENDOR: Yageo; VPC: 1/16W
R17 = PAS,R,large: DigiKey: RHM1271CT-ND; DigiReel: RHM1271DKR-ND; Family: passive; Index PN: 254; Lead Style: SMT; MFG: Rohm; Material: chip; P/D_NUM: UCR03EWPFSR039; Part Number: UCR03EWPFSR039; Part Specific: RES 0.039 OHM 1/4W 1% 0603; Tolerance: 1%; Type: resistor; VPC: 1/4W; Vendor: Rohm
R18 R20 = PAS,R,large: DigiKey: P10.0KLCT-ND; DigiReel: P10.0KLDKR-ND; Family: passive; Index PN: 680; Lead Style: SMT; MFG: Panasonic; Material: chip; P/D_NUM: ERJ-2RKF1002X; Part Number: ERJ-2RKF1002X; Part Specific: RES SMD 10K OHM 1% 1/10W 0402; Power: 1/16W; Tolerance: 1%; Type: resistor; VPC: 1/16W; Vendor: Panasonic
R19 = PAS,R,large: DigiKey: P300LCT-ND; DigiReel: P300LDKR-ND; Family: passive; Index PN: 1053; Lead Style: SMT; MFG: Panasonic; Material: chip; P/D_NUM: ERJ-2RKF3000X; Part Number: ERJ-2RKF3000X; Part Specific: RES 300 OHM 1/10W 1% 0402 SMD; TOLERANCE: 1%; Type: resistor; VPC: 1/16W; Vendor: Panasonic
R21 R23 R24 = PAS,R,large: DigiKey: P30.0KLCT-ND; DigiReel: P30.0KLDKR-ND; Family: passive; Index PN: 909; Lead Style: SMT; MFG: Panasonic; Material: chip; P/D_NUM: ERJ-2RKF3002X; Part Number: ERJ-2RKF3002X; Part Specific: RES 30.0K OHM 1/10W 1% 0402 SMD; Power: 1/16W; Tolerance: 1%; Type: resistor; VPC: 1/16W; Vendor: Panasonic
R22 = PAS,R,large: DigiKey: P0.0JCT-ND; DigiReel: P0.0JDKR-ND; Family: passive; Index PN: 687; Lead Style: SMT; MFG: Panasonic; Material: chip; P/D_NUM: ERJ-2GE0R00X; Part Number: ERJ-2GE0R00X; Part Specific: RES 0.0 OHM 1/16W 0402 SMD; Power: 1/16W; Tolerance: Jumper; Type: resistor; VPC: 1/16W; Vendor: Panasonic
R30 = PAS,R,large: DigiKey: YAG3111CT-ND; DigiReel: YAG3111DKR-ND; Family: passive; Lead Style: SMT; MFG: Yageo; Material: chip; P/D_NUM: RC0402FR-0730R1L; Part Number: RC0402FR-0730R1L; Part Specific: RES 30.1 OHM 1/16W 1% 0402 SMD; Power: 1/16W; Tolerance: 1%; Type: resistor; VPC: 1/16W; Vendor: Yageo
RT1 = PAS,THERMISTOR,large: DigiKey: 490-4803-1-ND; DigiReel: 490-4803-6-ND; Family: passive; Index PN: 910; Lead Style: SMT; MFG: Murata; P/D_NUM: NCP15WF104F03RC; Part Number: NCP15WF104F03RC; Part Specific: THERMISTOR 100K OHM NTC 0402 SMD; TOLERANCE: 1%; Type: thermistor; VENDOR: Murata
U3 = TIDLP,PAD2005,_C3: DigiKey: ---; DigiReel: ---; Family: power; Index PN: 1201; Lead Style: SMT; MFG: Texas Instruments; P/D_NUM: DLPA2005ERSLR; Part Number: DLPA2005ERSLR; Part Specific: Power & LED Driver IC for DLP PICO Projector; Pin Spacing: 0.4mm; Type: regulator; Vendor: Texas Instruments
C22 = PAS,CAP,NP,large_2: DigiKey: 445-1262-1-ND; DigiReel: 445-1262-6-ND; Family: passive; Index PN: 908; Lead Style: SMT; MFG: TDK; Material: x7r; P/D_NUM: C1005X7R1C103K; Part Number: C1005X7R1C103K; Part Specific: CAP CER 10000PF 16V X7R 10% 0402; TOLERANCE: 10%; Type: capacitor; VENDOR: TDK; VPC: 16V
C24 C39 = PAS,CAP,NP,large_2: DigiKey: 587-3245-1-ND; DigiReel: 587-3245-6-ND; Family: passive; Lead Style: SMT; MFG: Taiyo Yuden; Material: x5r; P/D_NUM: TMK105BJ105MV-F; Part Number: TMK105BJ105MV-F; Part Specific: CAP CER 1.0UF 25V X5R 0402; TOLERANCE: 20%; Type: capacitor; VENDOR: Taiyo Yuden; VPC: 25V
F1 F2 = PAS,FERRITE_BEAD,3: DigiKey: 490-5202-1-ND; DigiReel: 490-5202-6-ND; Family: passive; Index PN: 999; Install: Y; Lead Style: SMT; MFG: Murata; Part Specific: FERRITE CHIP 80 OHM 1500MA 0402; Type: ferrite bead; VENDOR: Murata; VPC: 1500mA
TPGND1 TPGND2 TPGND4 = EM,TERM,TESTPOINT: DigiKey: 5001K-ND; DigiReel: ---; Family: electro/mechanical; Index PN: 946; Install: Y; Lead Style: TH; MFG: Keystone; P/D_NUM: 5001; Part Number: 5001; Part Specific: TEST POINT PC MINI .040inD BLACK; Type: terminal; Vendor: Keystone
TPGND3 = EM,TERM,TESTPOINT: DigiKey: 5001K-ND; DigiReel: ---; Family: electro/mechanical; Index PN: 946; Install: DNI; Lead Style: TH; MFG: Keystone; P/D_NUM: 5001; Part Number: 5001; Part Specific: TEST POINT PC MINI .040inD BLACK; Type: terminal; Vendor: Keystone
U1 = TIDLP,DPP3438,no_DSI: DigiReel: ---; Family: processor; Install: Y; Lead Style: SMT; MFG: Texas Instruments; P/D_NUM: DLPC3470ZEZ; Part Number: DLPC3470ZEZ; Part Specific: DLP-PICO Processor; Type: dlp; Vendor: Texas Instruments

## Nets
DGND: C1.1(P) C2.2(N) C3.2(N) C4.2(N) C5.2(N) C6.2(N) C7.2(N) C8.2(N) C9.2(N) C10.2(N) C11.1(P) C12.2(N) C13.2(N) C14.2(N) C15.2(N) C16.2(N) C17.2(N) C18.1(P) C19.2(N) C20.2(N) C21.2(N) C24.2(N) C25.2(N) C26.2(N) C27.2(N) C28.2(N) C29.2(N) C30.2(N) C31.2(N) C32.2(N) C33.2(N) C34.2(N) C35.2(N) C36.2(N) C37.2(N) C38.2(N) C39.2(N) C40.2(N) C41.2(N) C42.2(N) C43.2(N) C44.2(N) C45.2(N) C46.2(N) C47.2(N) C48.2(N) C49.1(P) C50.1(P) C51.1(P) C52.1(P) C53.1(P) C54.2(N) F1.2(N2) J1.2 J1.7 J1.12 J1.15 J1.20 J1.21 J1.22 J1.25 J1.26 J1.30 J1.31 J1.36 J1.39 J1.44 J1.48 J1.49 J4.1 J5.G1 J5.G2 J5.G3 J5.G4 R5.1(N1) R6.1(N1) R17.2(N2) R23.2(N2) R26.1(N1) R27.1(N1) R29.1(N1) RT1.2 TPGND1.1(P1) TPGND2.1(P1) TPGND3.1(P1) TPGND4.1(P1) TPGND5.1(P1) TPGND6.1(P1) U1.C4(VSS) U1.C6(VSS) U1.C8(VSS) U1.C10(HWTEST_EN) U1.D6(VSS) U1.D8(VSS) U1.D10(VSS) U1.E4(VSS) U1.E13(VSS) U1.F4(VSS) U1.F6(VSS) U1.F7(VSS) U1.F8(VSS) U1.F9(VSS) U1.F10(VSS) U1.G4(VSS) U1.G6(VSS) U1.G7(VSS) U1.G8(VSS) U1.G9(VSS) U1.G10(VSS) U1.G12(VSS) U1.G13(VSS) U1.H4(VSS) U1.H6(VSS) U1.H7(VSS) U1.H8(VSS) U1.H9(VSS) U1.H10(VSS) U1.H12(VSS) U1.J3(VSS) U1.J6(VSS) U1.J7(VSS) U1.J8(VSS) U1.J9(VSS) U1.J10(VSS) U1.J13(VSS) U1.K4(VSS) U1.K6(VSS) U1.K7(VSS) U1.K8(VSS) U1.K9(VSS) U1.K10(VSS) U1.K12(VSS) U1.L3(VSS) U1.M4(VSS) U1.M5(VSS) U1.M8(VSS) U1.M12(VSS) U2.4(GND) U3.5(AGND1) U3.12(PGNDR) U3.20(GND) U3.23(PGNDCM) U3.45(PGNDL_1) U3.46(PGNDL_2) U3.PAD(THERMAL) U4.2(GND) U5.3(GND) U6.2(GND)
P5V_VIN: C3.1(P) C4.1(P) C6.1(P) C7.1(P) C8.1(P) C11.2(N) C16.1(P) C52.2(N) J4.2 J5.55(P55) J5.56(P56) J5.57(P57) J5.58(P58) J5.59(P59) J5.60(P60) U3.1(VINL) U3.2(VINL) U3.10(VINR) U3.18(VINA) U3.25(VINC)
V2V5: C14.1(P) U3.19(V2V5) V2V5.1(P1)
V6V: C18.2(N) U3.35(V6V) V6V.1(P1)
VDD_PLL: C22.2(N) C23.1(P) F2.1(N1) U1.H2(VDD_PLLM) U1.J2(VDD_PLLD)
VSS_PLL: C22.1(P) C23.2(N) F1.1(N1) U1.G3(VSS_PLLM) U1.H3(VSS_PLLD)
3DR: J3.2 R6.2(N2) U1.N6(3DR)
3DR_BF: J4.5 U5.2(A)
3DR_D: J3.1 J5.31(P31)
3DR_S: J3.3 R35.1(N1) U5.4(Y)
BLU_CATHODE: J2.4 U3.37(SW6)
CAL_PWR: R24.2(N2) U1.J15(GPIO_13)
CMP_OUT: U1.A12(CMP_OUT) U3.28(CMP_OUT)
CMP_PWM: R20.1(N1) U1.A15(CMP_PWM)
DATEN_CMD: J5.17(P17) U1.P2(DATEN_CMD)
DMD_DEN_ARSTZ: J1.4 U1.B1(DMD_DEN_ARSTZ)
DMD_HS_CLK_N: J1.14 U1.B7(DMD_HS_CLK_N)
DMD_HS_CLK_P: J1.13 U1.A7(DMD_HS_CLK_P)
DMD_HS_WDATAA_N: J1.19 U1.B11(DMD_HS_WDATAA_N)
DMD_HS_WDATAA_P: J1.18 U1.A11(DMD_HS_WDATAA_P)
DMD_HS_WDATAB_N: J1.17 U1.B10(DMD_HS_WDATAB_N)
DMD_HS_WDATAB_P: J1.16 U1.A10(DMD_HS_WDATAB_P)
DMD_HS_WDATAC_N: J1.32 U1.B9(DMD_HS_WDATAC_N)
DMD_HS_WDATAC_P: J1.33 U1.A9(DMD_HS_WDATAC_P)
DMD_HS_WDATAD_N: J1.34 U1.B8(DMD_HS_WDATAD_N)
DMD_HS_WDATAD_P: J1.35 U1.A8(DMD_HS_WDATAD_P)
DMD_HS_WDATAE_N: J1.40 U1.B6(DMD_HS_WDATAE_N)
DMD_HS_WDATAE_P: J1.41 U1.A6(DMD_HS_WDATAE_P)
DMD_HS_WDATAF_N: J1.42 U1.B5(DMD_HS_WDATAF_N)
DMD_HS_WDATAF_P: J1.43 U1.A5(DMD_HS_WDATAF_P)
DMD_HS_WDATAG_N: J1.11 U1.B4(DMD_HS_WDATAG_N)
DMD_HS_WDATAG_P: J1.10 U1.A4(DMD_HS_WDATAG_P)
DMD_HS_WDATAH_N: J1.9 U1.B3(DMD_HS_WDATAH_N)
DMD_HS_WDATAH_P: J1.8 U1.A3(DMD_HS_WDATAH_P)
DMD_LS_CLK: J1.6 R3.1(N1)
DMD_LS_RDATA: J1.3 U1.B2(DMD_LS_RDATA)
DMD_LS_WDATA: J1.5 R4.1(N1)
DPP_MOSI: R14.2(N2) U1.B13(SPI0_DOUT)
DPP_PLLI: C2.1(P) R2.2(N2) U1.H1(PLL_REFCLK_I) X1.1(P)
DPP_PLLO: R1.1(N1) R2.1(N1) U1.J1(PLL_REFCLK_O)
DPP_SPI0_MISO: R31.1(N1) U2.2(DO)
DPP_SPICLK: R15.2(N2) U1.A13(SPI0_CLK)
DPP_SPICSZ0: R13.2(N2) U1.A14(SPI0_CSZ0)
GPIO_1: R11.1(N1) R12.2(N2) U1.C15(GPIO_1)
GPIO_2: R9.2(N2) R10.1(N1) U1.D14(GPIO_2)
GPIO_3: R7.1(N1) R8.2(N2) U1.D15(GPIO_3)
GPIO_4: GPIO_4.1(P1) U1.E14(GPIO_4)
GPIO_5: GPIO_5.1(P1) U1.E15(GPIO_5)
GPIO_6: U1.F14(GPIO_6) U4.1(1A)
GPIO_6_BF: J4.3 R36.2(N2) U4.6(1Y)
GPIO_7: U1.F15(GPIO_7) U4.3(2A)
GPIO_7_BF: J4.4 R37.2(N2) U4.4(2Y)
GPIO_14: GPIO_14.1(P1) U1.K14(GPIO_14)
GPIO_15: GPIO_15.1(P1) U1.K15(GPIO_15)
GPIO_16: GPIO_16.1(P1) U1.L14(GPIO_16)
GPIO_17: GPIO_17.1(P1) U1.L15(GPIO_17)
GPIO_18: GPIO_18.1(P1) U1.M14(GPIO_18)
GPIO_19: GPIO_19.1(P1) U1.M15(GPIO_19)
GRN_CATHODE: J2.3 U3.38(SW5)
HOST_IRQ: J5.35(P35) R25.2(N2) U1.N8(HOST_IRQ)
HSYNC_CS: J5.27(P27) U1.N5(HSYNC_CS)
IIC0_SCL: J5.43(P43) U1.N10(IIC0_SCL)
IIC0_SDA: J5.39(P39) U1.N9(IIC0_SDA)
INTZ: R28.2(N2) U1.C13(PARKZ) U3.6(INTz)
JTAG_TRSTZ: R26.2(N2) U1.P11(JTAGTRSTZ)
L1: L1.2 U3.47(L1_1) U3.48(L1_2)
L2: L1.1 U3.43(L2_1) U3.44(L2_2)
LED_ANODE: C12.1(P) C13.1(P) C15.1(P) C54.1(P) J2.1 U3.41(VLED_1) U3.42(VLED_2)
LED_SEL_0: U1.B15(LED_SEL_0) U3.31(LED_SEL0)
LED_SEL_1: U1.B14(LED_SEL_1) U3.34(LED_SEL1)
LS2_PWR: LS2_PWR.1(P1) U1.J14(GPIO_12)
LS_CLK: R3.2(N2) U1.A1(DMD_LS_CLK)
LS_PWR: LS_PWR.1(P1) U1.G15(GPIO_9)
LS_WDATA: R4.2(N2) U1.A2(DMD_LS_WDATA)
P1P1V: C17.1(P) C24.1(P) C26.1(P) C27.1(P) C28.1(P) C33.1(P) C34.1(P) C36.1(P) C40.1(P) C42.1(P) C43.1(P) C45.1(P) C46.1(P) C47.1(P) F2.2(N2) L3.2 U1.C3(VDDLP12) U1.C5(VDD) U1.D3(VDD) U1.D5(VDD) U1.D7(VDD) U1.D9(VDD) U1.D12(VDD) U1.D13(VDD) U1.E3(VDD) U1.F13(VDD) U1.H13(VDD) U1.J4(VDD) U1.J12(VDD) U1.K3(VDD) U1.L4(VDD) U1.L12(VDD) U1.L13(VDD) U1.M6(VDD) U1.M9(VDD) U1.M10(VDD) U3.29(VCORE)
P1P8V: C19.1(P) C25.1(P) C31.1(P) C35.1(P) C37.1(P) C39.1(P) C44.1(P) C48.1(P) C53.2(N) J1.1 J1.37 J1.38 J1.50 J5.52(P52) R7.2(N2) R10.2(N2) R11.2(N2) R28.1(N1) U1.C7(VCC) U1.C9(VCC) U1.D4(VCC) U1.E12(VCC) U1.F12(VCC) U1.K13(VCC) U1.M11(VCC) U3.21(LS_OUT) U3.32(VSPI)
P1P8V_MAIN: J5.54(P54) U3.22(LS_IN) U4.5(Vcc) U6.5(Vcc)
P3P3V_SB: C29.1(P) C30.1(P) C32.1(P) C38.1(P) C41.1(P) J1.29 J5.48(P48) J5.50(P50) R25.1(N1) R32.1(N1) R35.2(N2) U1.D11(VCC_FLSH) U1.M3(VCC_INTF) U1.M7(VCC_INTF) U1.N3(VCC_INTF) U1.N7(VCC_INTF) U2.3(~{WP}) U2.7(~{HOLD}) U2.8(VCC3)
PCLK: J5.19(P19) U1.P3(PCLK)
PDATA0: J5.9(P9) U1.K2(PDATA_0)
PDATA1: J5.1(P1) U1.K1(PDATA_1)
PDATA2: J5.11(P11) U1.L2(PDATA_2)
PDATA3: J5.3(P3) U1.L1(PDATA_3)
PDATA4: J5.13(P13) U1.M2(PDATA_4)
PDATA5: J5.5(P5) U1.M1(PDATA_5)
PDATA6: J5.15(P15) U1.N2(PDATA_6)
PDATA7: J5.7(P7) U1.N1(PDATA_7)
PDATA8: J5.4(P4) U1.R1(PDATA_8)
PDATA9: J5.6(P6) U1.R2(PDATA_9)
PDATA10: J5.8(P8) U1.R3(PDATA_10)
PDATA11: J5.21(P21) U1.P4(PDATA_11)
PDATA12: J5.10(P10) U1.R4(PDATA_12)
PDATA13: J5.25(P25) U1.P5(PDATA_13)
PDATA14: J5.12(P12) U1.R5(PDATA_14)
PDATA15: J5.29(P29) U1.P6(PDATA_15)
PDATA16: J5.14(P14) U1.R6(PDATA_16)
PDATA17: J5.33(P33) U1.P7(PDATA_17)
PDATA18: J5.16(P16) U1.R7(PDATA_18)
PDATA19: J5.37(P37) U1.P8(PDATA_19)
PDATA20: J5.18(P18) U1.R8(PDATA_20)
PDATA21: J5.41(P41) U1.P9(PDATA_21)
PDATA22: J5.20(P20) U1.R9(PDATA_22)
PDATA23: J5.45(P45) U1.P10(PDATA_23)
PDM_CVS_TE: J5.23(P23) R5.2(N2) U1.N4(PDM_CVS_TE)
PROJ_ON: J5.36(P36) U1.G14(GPIO_8) U3.27(PROJ_ON)
PWM_IN: R18.2(N2) U3.26(PWM_IN)
PWM_IN_CAP: C20.1(P) R18.1(N1) R19.1(N1) R20.2(N2)
PWR_TP_SEN: J4.8 J5.38(P38) J5.40(P40) R33.1(N1) R34.1(N1) R36.1(N1) R37.1(N1) U5.5(PWR)
RC_CHARGE: R19.2(N2) U1.H14(GPIO_10)
RED_CATHODE: J2.2 U3.39(SW4)
REF_VRST: R16.1(N1) U3.16(REF_VRST)
RESETZ: J5.53(P53) U1.C11(RESETZ) U3.4(RESETz)
RLIM: R17.1(N1) U3.36(RLIM_K) U3.40(RLIM)
SENS1: R23.1(N1) R24.1(N1) SENS1.1(P1) U3.33(SENS1)
SENS2: C21.1(P) R22.2(N2) SENS2.1(P1) U3.30(SENS2)
SPI0_CLK: CLK.1(P1) J1.23 J5.46(P46) R15.1(N1) R27.2(N2) U2.6(CLK)
SPI0_CSZ0: CSZ.1(P1) J1.28 J5.51(P51) R13.1(N1) R32.2(N2) U2.1(~{CS})
SPI0_MISO: J1.24 J5.47(P47) MIS0.1(P1) R29.2(N2) R31.2(N2) U1.B12(SPI0_DIN)
SPI0_MOSI: J1.27 J5.49(P49) MOSI.1(P1) R14.1(N1) U2.5(DIO)
SPI1_CLK: R12.1(N1) U3.7(SPI_CLK)
SPI1_CSZ0: R8.1(N1) U3.8(SPI_CSZ)
SPI1_DIN: R30.1(N1) U1.C14(GPIO_0)
SPI1_DIN_T: R30.2(N2) U3.9(SPI_DOUT)
SPI1_DOUT: R9.1(N1) U3.3(SPI_DIN)
SWC: L3.1 U3.24(SWC)
SWN: D1.1(P1) L2.2 U3.11(SWN)
SWP: L2.1 U3.13(SWP)
THERM_PWR: R21.2(N2) THERM.1(P1) U1.H15(GPIO_11)
THERMISTOR: R21.1(N1) R22.1(N1) RT1.1
TSTPT_0: J5.22(P22) U1.R12(TSTPT_0)
TSTPT_1: J5.24(P24) U1.R13(TSTPT_1)
TSTPT_2: J5.26(P26) U1.R14(TSTPT_2)
TSTPT_3: J5.28(P28) U1.R15(TSTPT_3)
TSTPT_4: U1.P14(TSTPT_4) U6.1(1A)
TSTPT_4_BF: J4.7 R33.2(N2) U6.6(1Y)
TSTPT_5: U1.P15(TSTPT_5) U6.3(2A)
TSTPT_5_BF: J4.6 R34.2(N2) U6.4(2Y)
TSTPT_6: J5.30(P30) U1.N14(TSTPT_6)
TSTPT_7: J5.32(P32) U1.N15(TSTPT_7)
VBIAS: C9.1(P) C51.2(N) J1.46 U3.15(VBIAS) VBIAS.1(P1)
VOFS: C10.1(P) C50.2(N) J1.47 U3.17(VOFS) VOFS.1(P1)
VRST: C5.1(P) C49.2(N) D1.2(P2) J1.45 R16.2(N2) U3.14(CNTR_VRST) VRST.1(P1)
VSYNC_WE: J5.2(P2) U1.P1(VSYNC_WE)
X_OUT2: C1.2(N) R1.2(N2) X1.3(N)

Not connected (* = marked no-connect by the designer): J5 34(P34) 42(P42) 44(P44); U1 C1(NC9)* C2(NC10)* C12(SPI0_CSZ1)* D1(NC7)* D2(NC8)* E1(NC1)* E2(NC2)* F1(NC5)* F2(NC6)* F3(NC11)* G1(NC3)* G2(NC4)* M13(JTAGTMS1)* N11(JTAGTMS2)* N12(JTAGTDO2)* N13(JTAGTDO1)* P12(JTAGTCK)* P13(JTAGTDI)* R10(IIC1_SDA)* R11(IIC1_SCL)*

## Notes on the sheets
sheet 1
- Connect the RLIM_K pin to the
  SENSE Resistor (R1) with it's own
  trace. Consult the PAD2005 data
  sheet for details.
- VOFS= 10.0V
- LABB
- VBIAS= 18V
- VRST= -14V
- WPC
- DLPC3470 GPIO's, DLPA2005
sheet 3
- DMD Interface
sheet 4
- Revisions
- Rev. E.0 : Development version
  Rev. E.1 : Marked R16 as DNI
                   Changed C53 cap value to 4.7uF
                   Changed U2 part number to W25Q32JVSSIQ
                   Changed title to accommodate new part-number
  Rev. A    : Removed ESD number, Changed to Rev A
  Rev. A.1 : Changed R6 to DNI for light control input
  Rev. B    : Changed pull-up voltage for 3DR_S on R35 to 3.3V
sheet 5
- DLPC3470 Clock, Reset, SPI and Flash Memory
- X1 and passives  should be
  placed very close to the DPP pins.
- Note: DLPC3470 3DR pin expects a high level of 3.3V
- SENSING SELECTION
- DLPC3470, Sensing interface, Flash
sheet 6
- DLPC3470 Power
sheet 7
- Front-End Connection
